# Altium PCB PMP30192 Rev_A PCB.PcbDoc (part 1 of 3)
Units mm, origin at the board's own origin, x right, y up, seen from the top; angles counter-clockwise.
Board outline 142.24 x 157.48 mm, 4 copper layers (Top Layer, Signal Layer 1, Signal Layer 2, Bottom Layer), stack 1.647 mm thick; 198 components, 99 nets, 479 pads, 192 vias.
Unrouted connection lines stored in the file: 2.
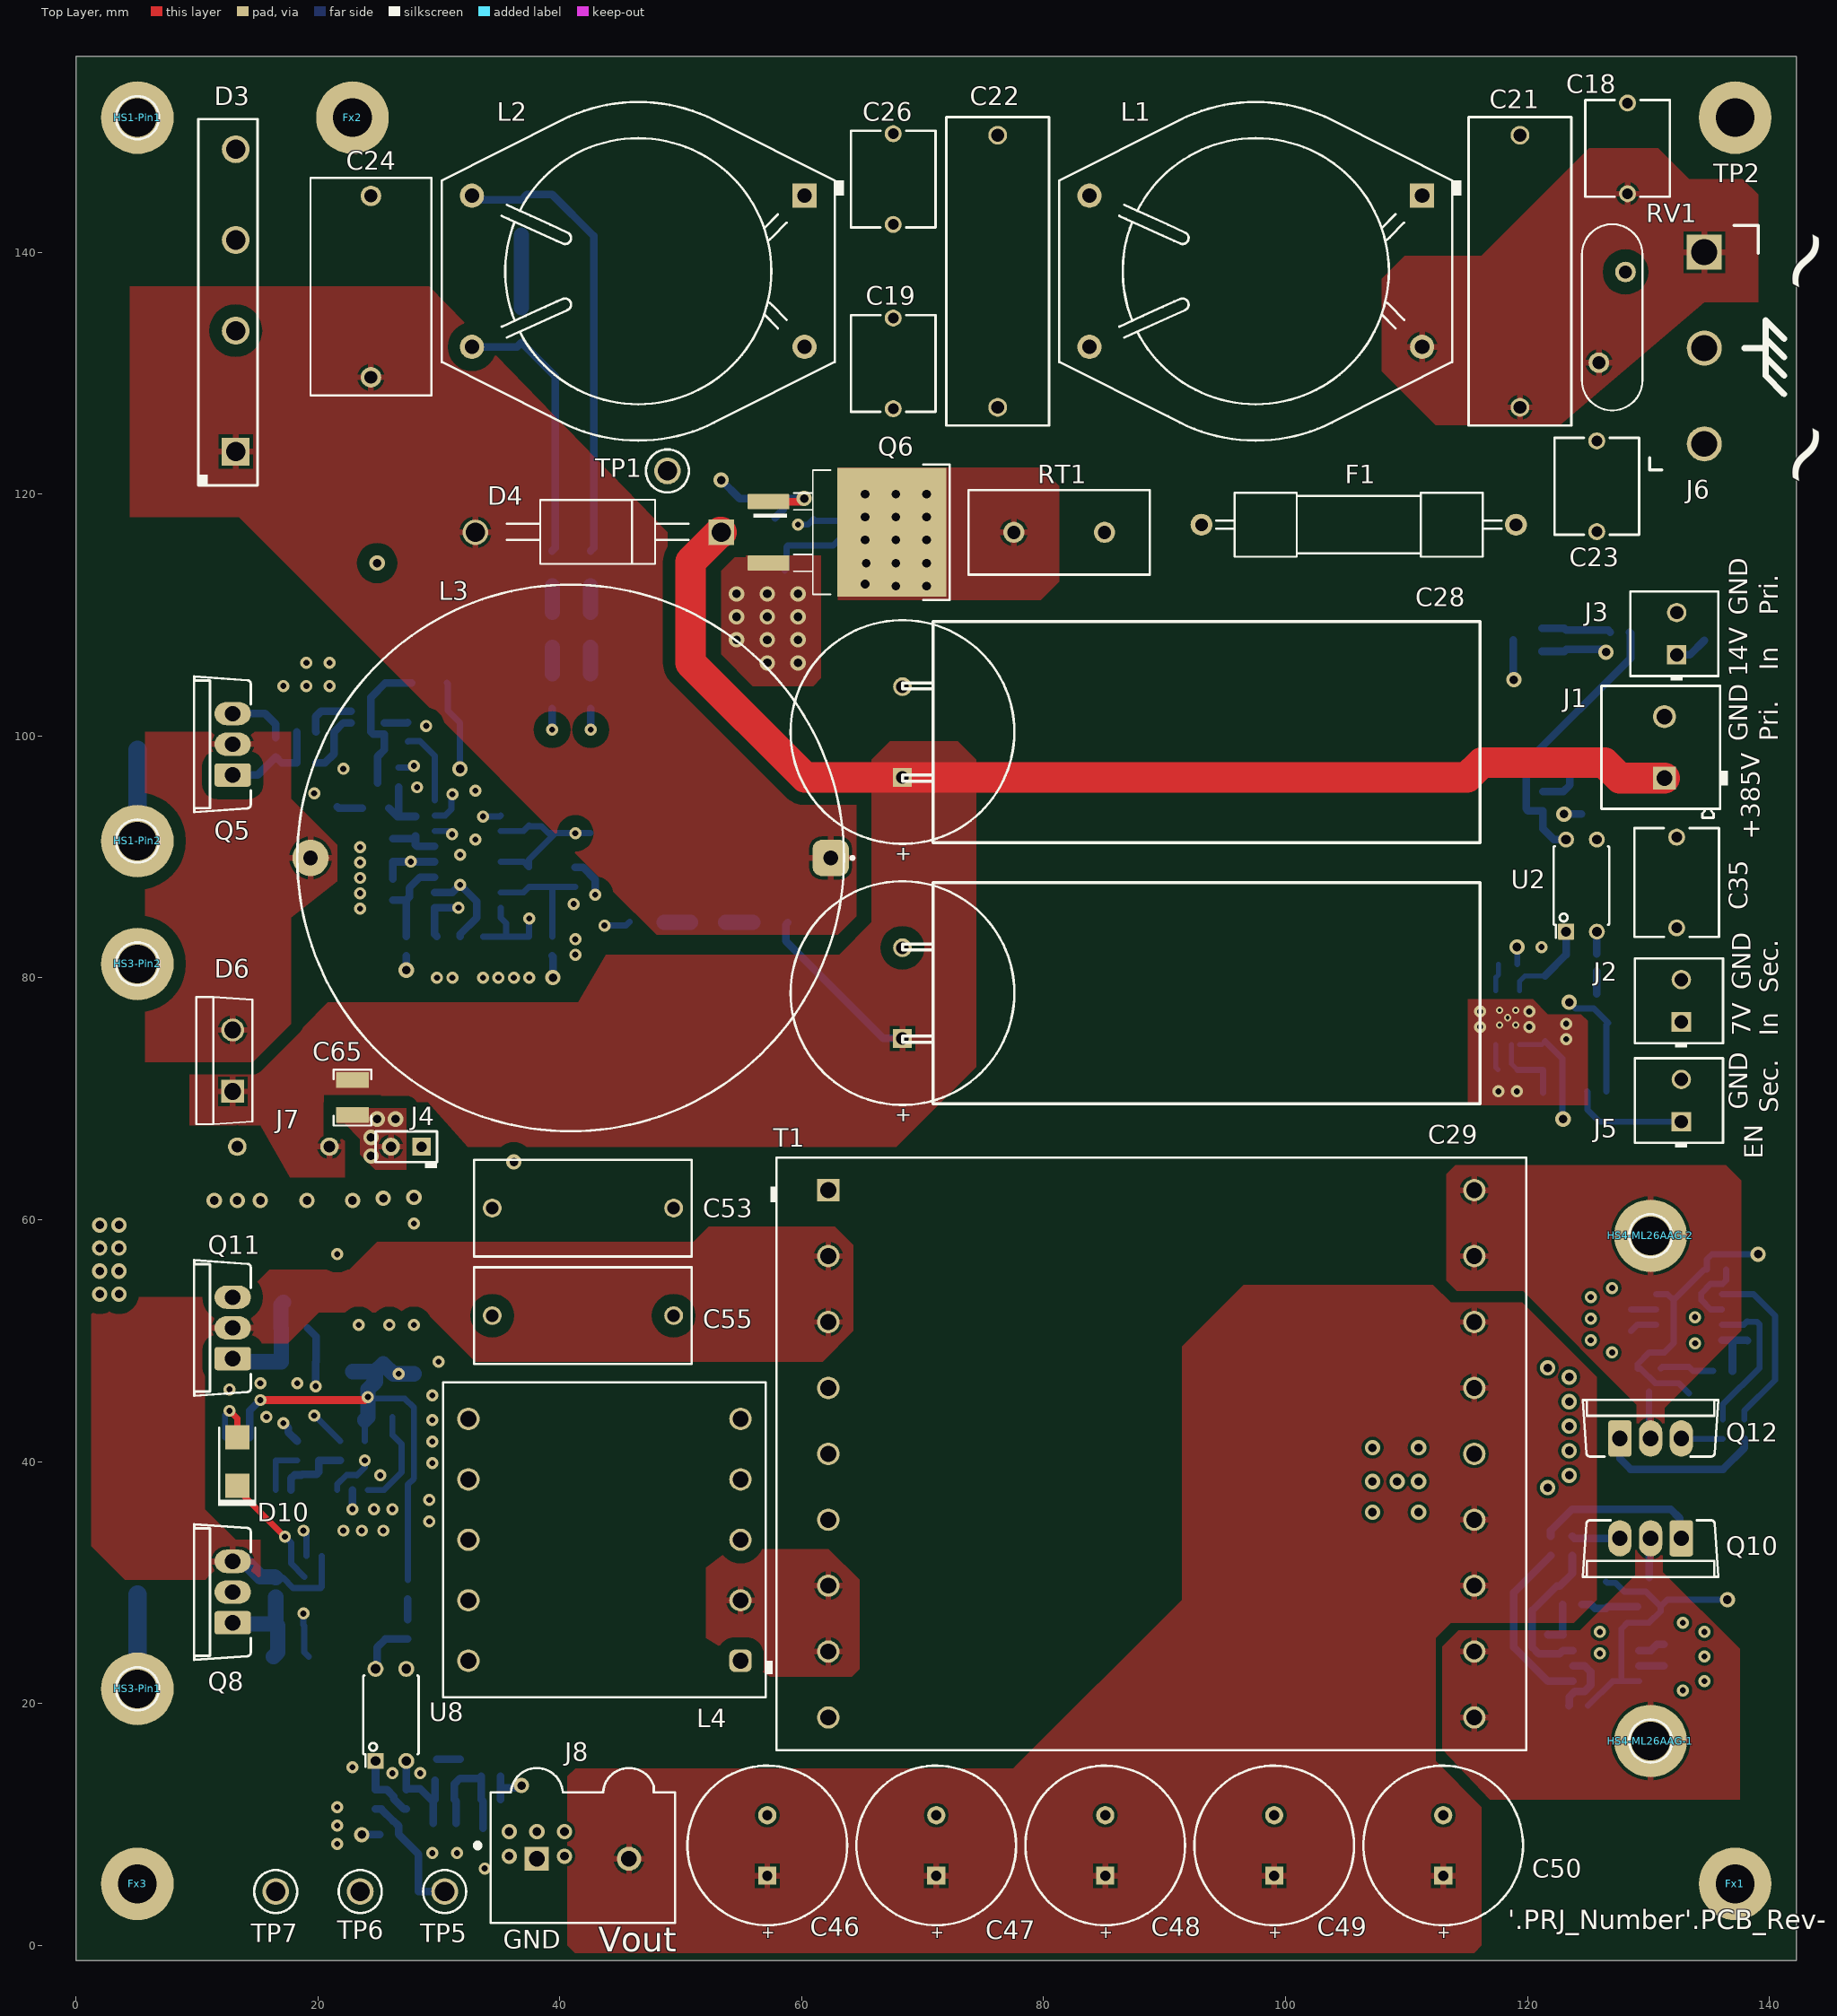
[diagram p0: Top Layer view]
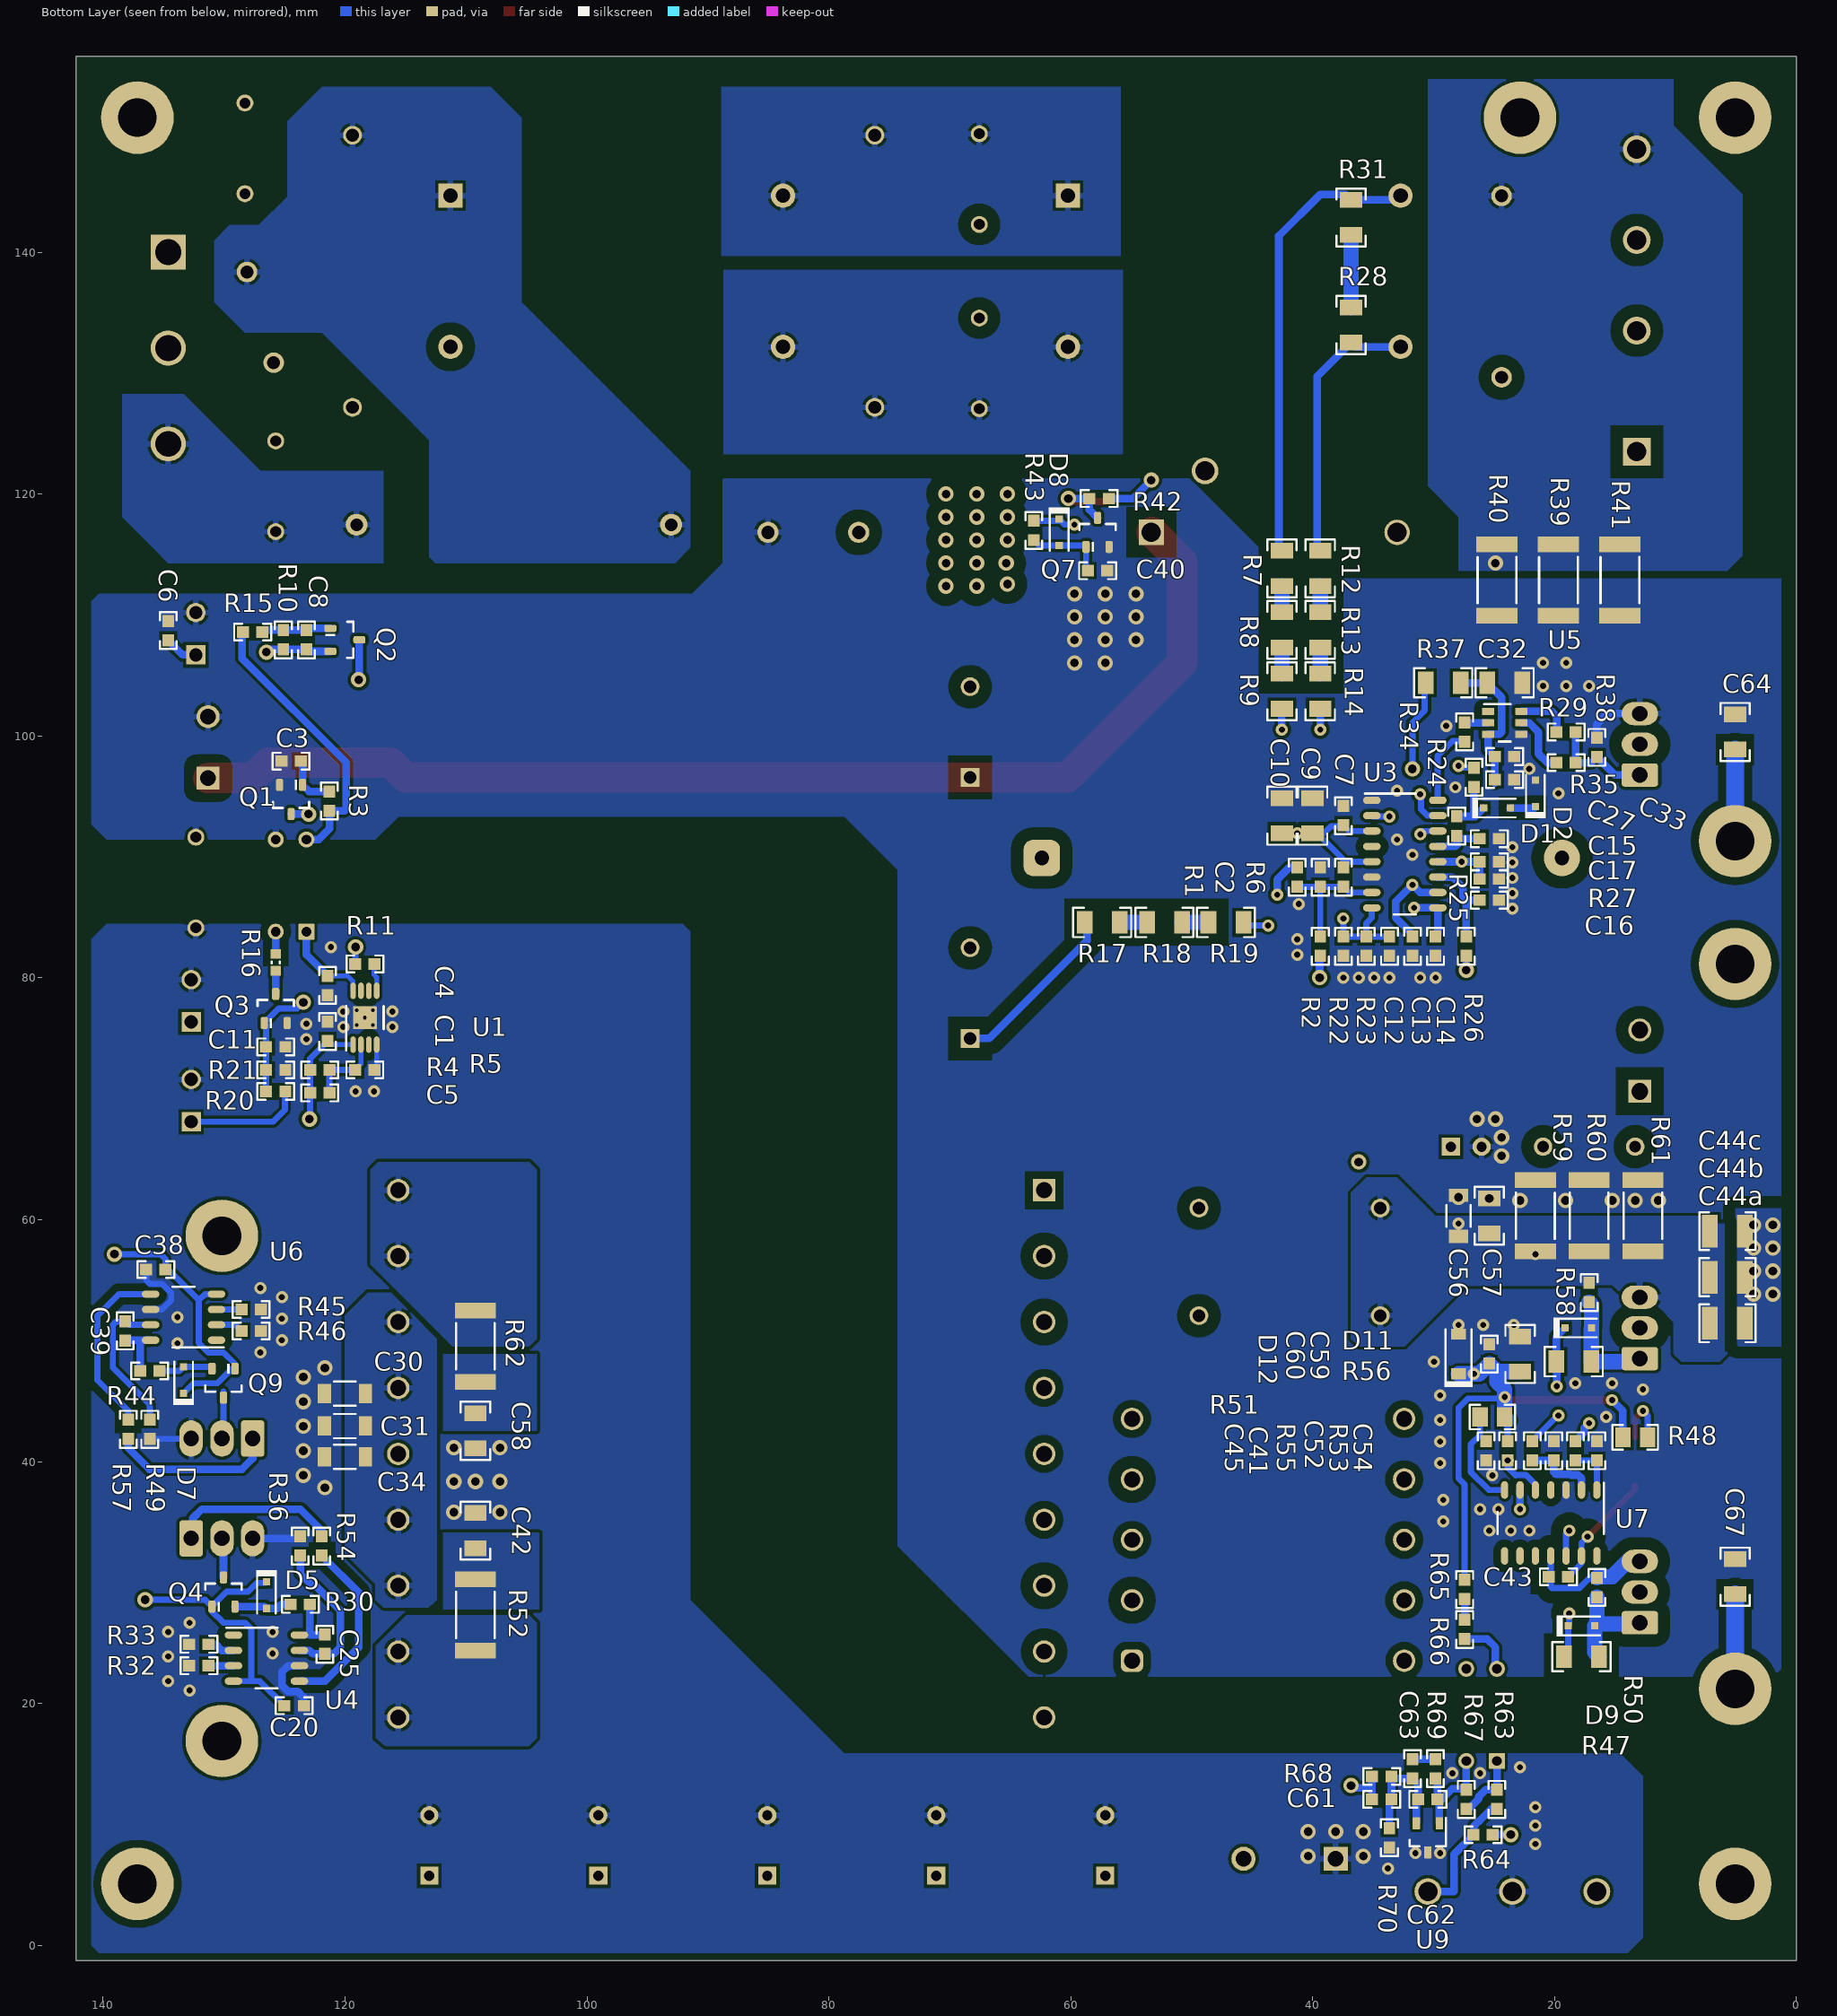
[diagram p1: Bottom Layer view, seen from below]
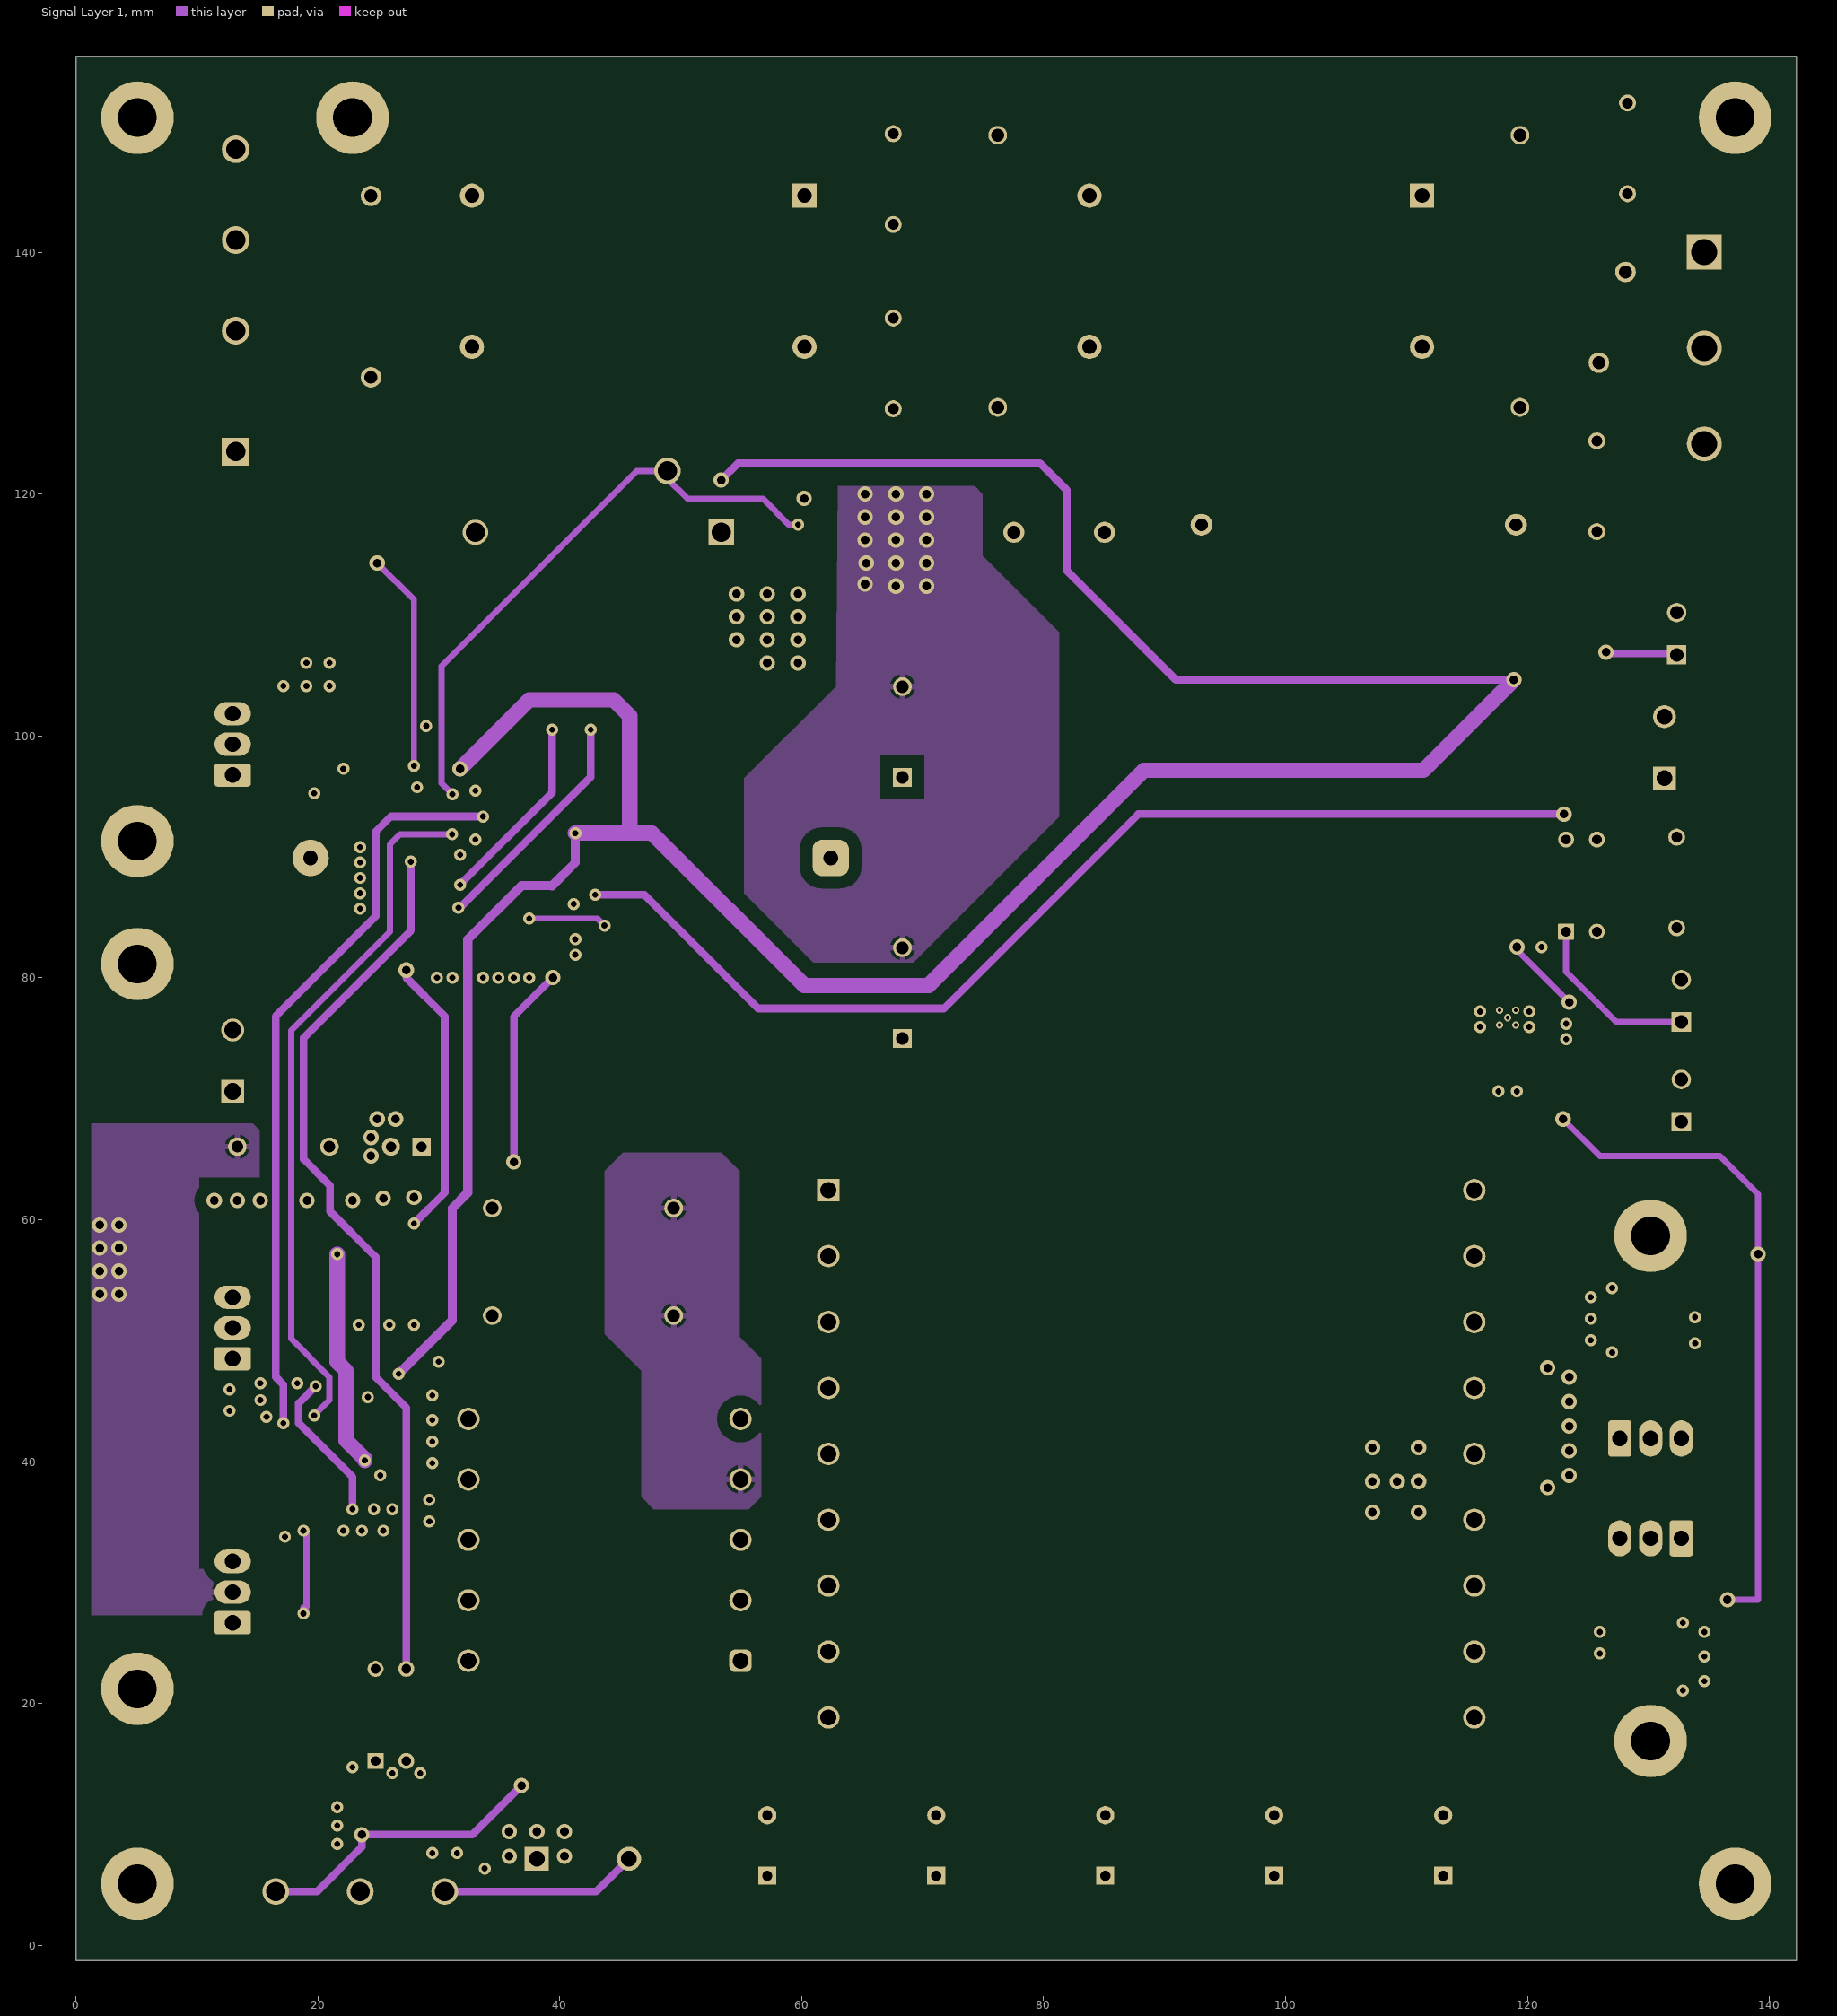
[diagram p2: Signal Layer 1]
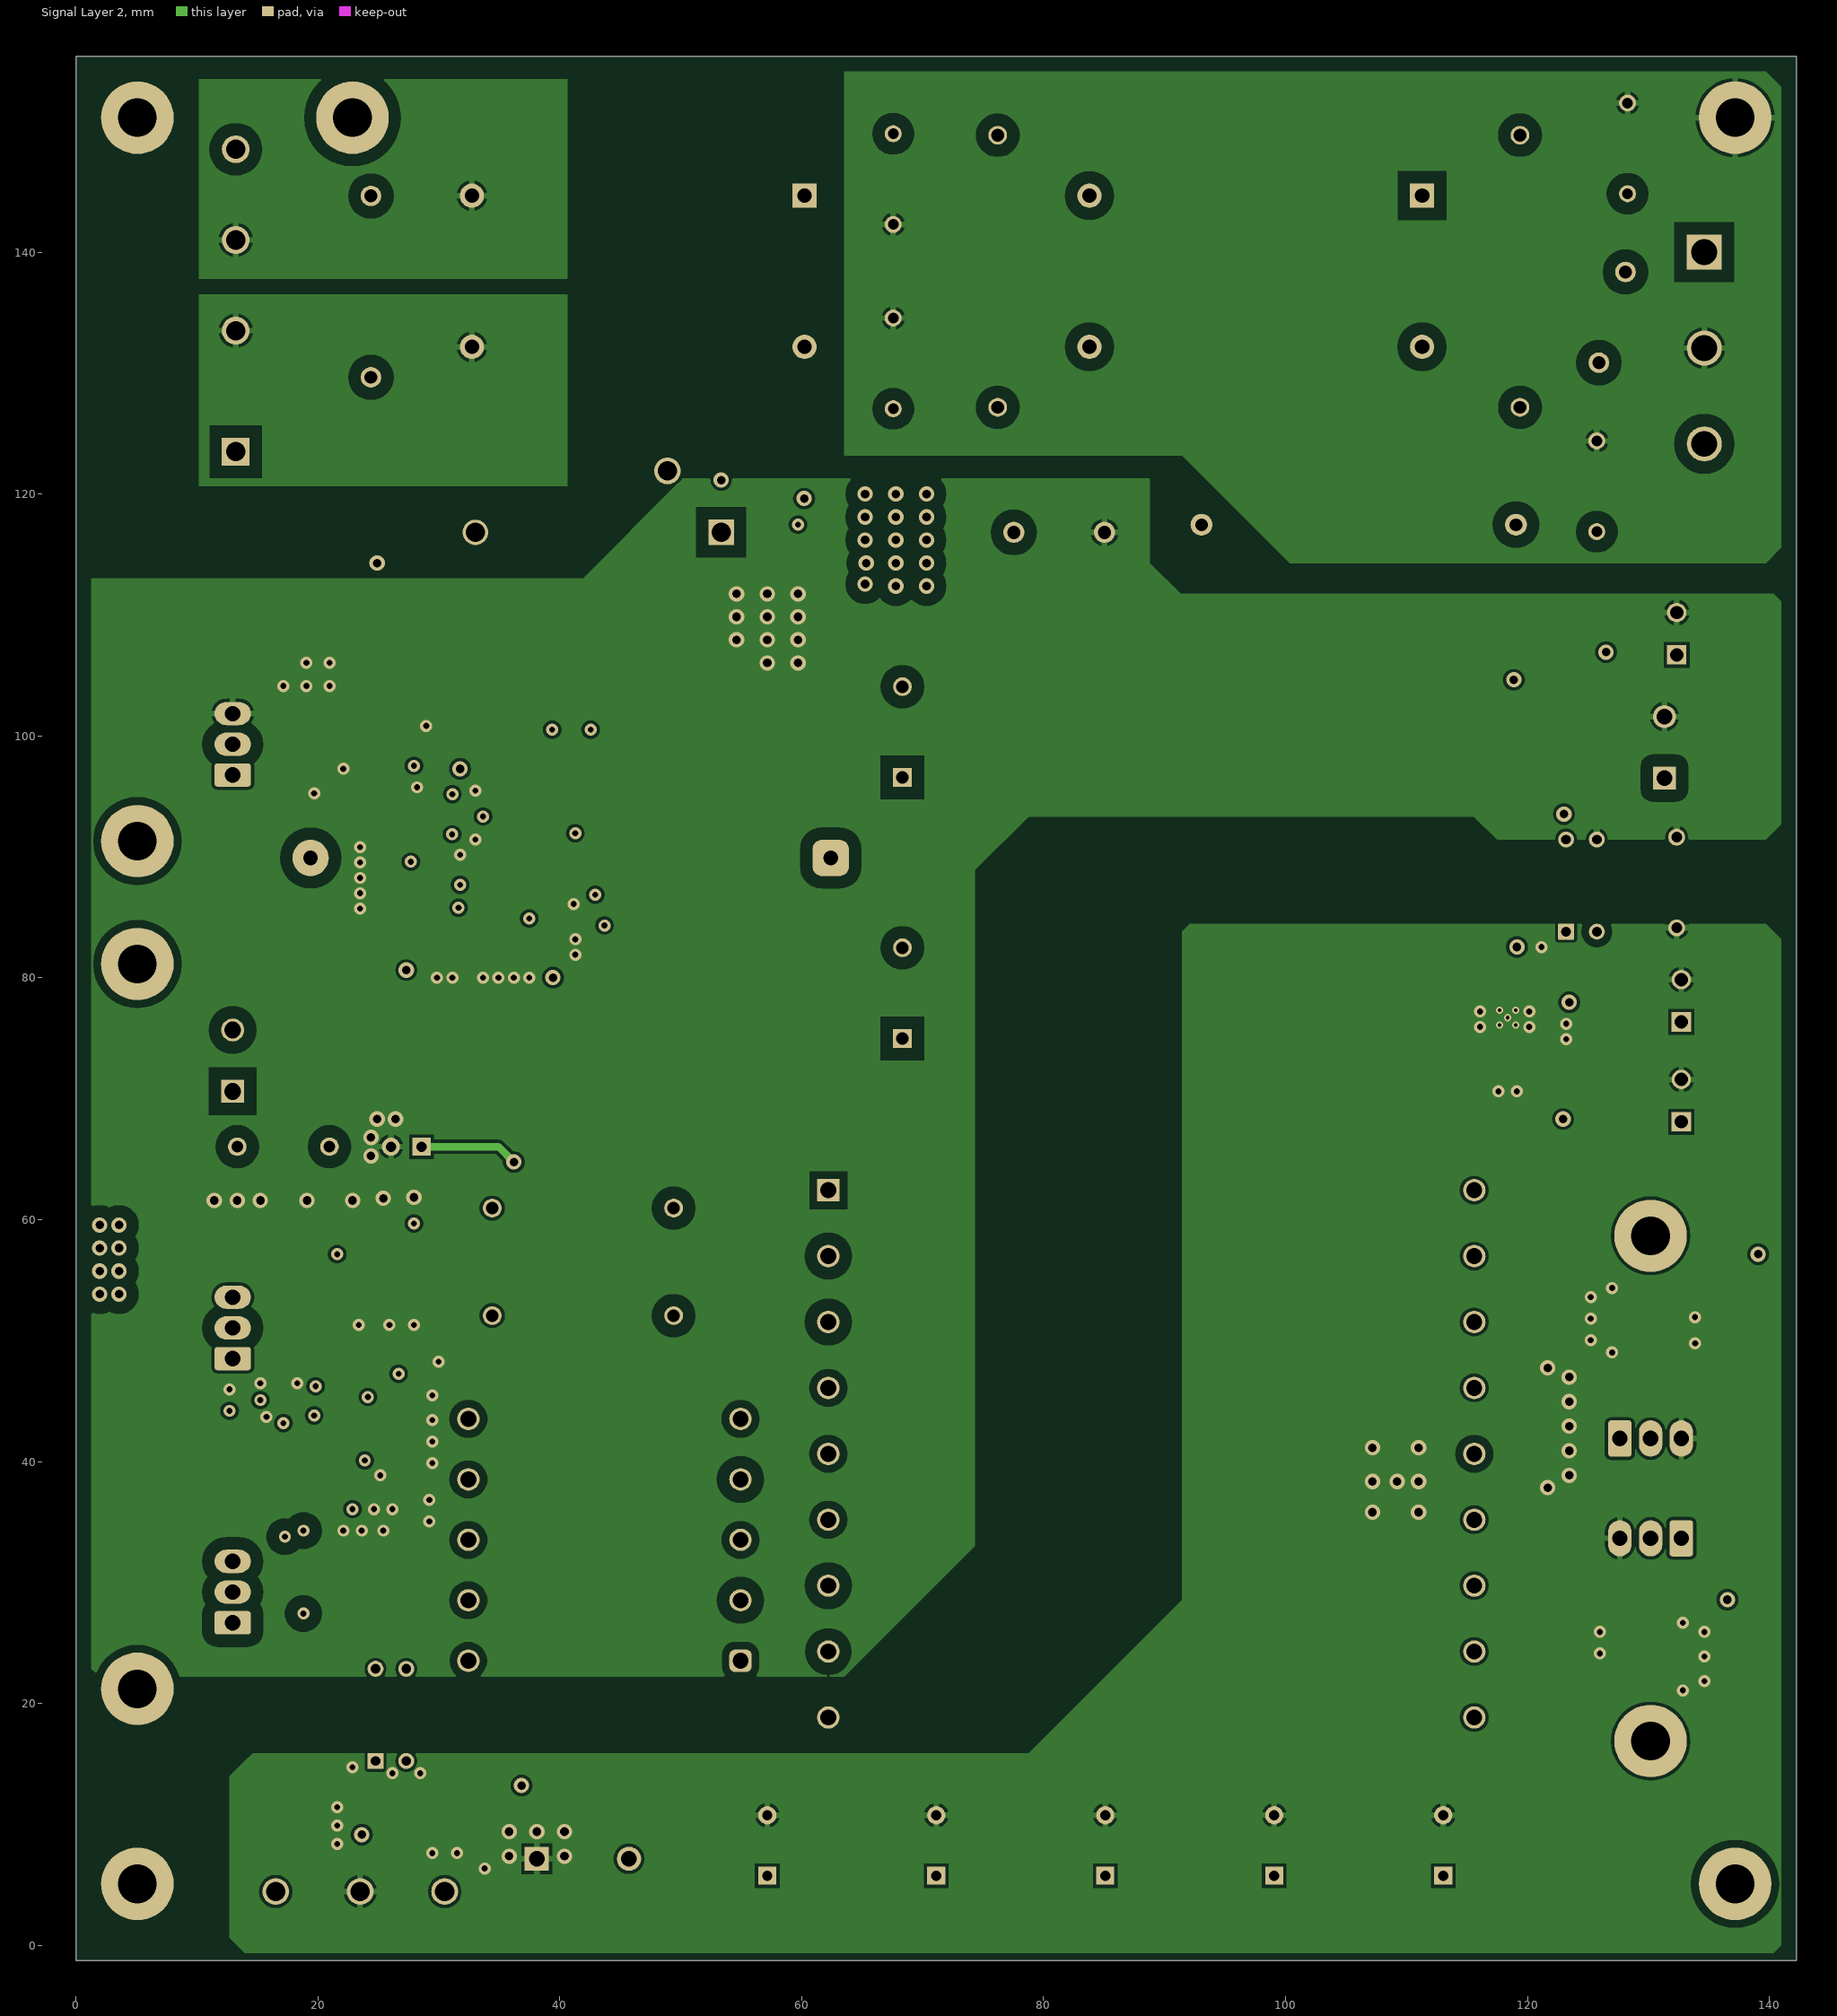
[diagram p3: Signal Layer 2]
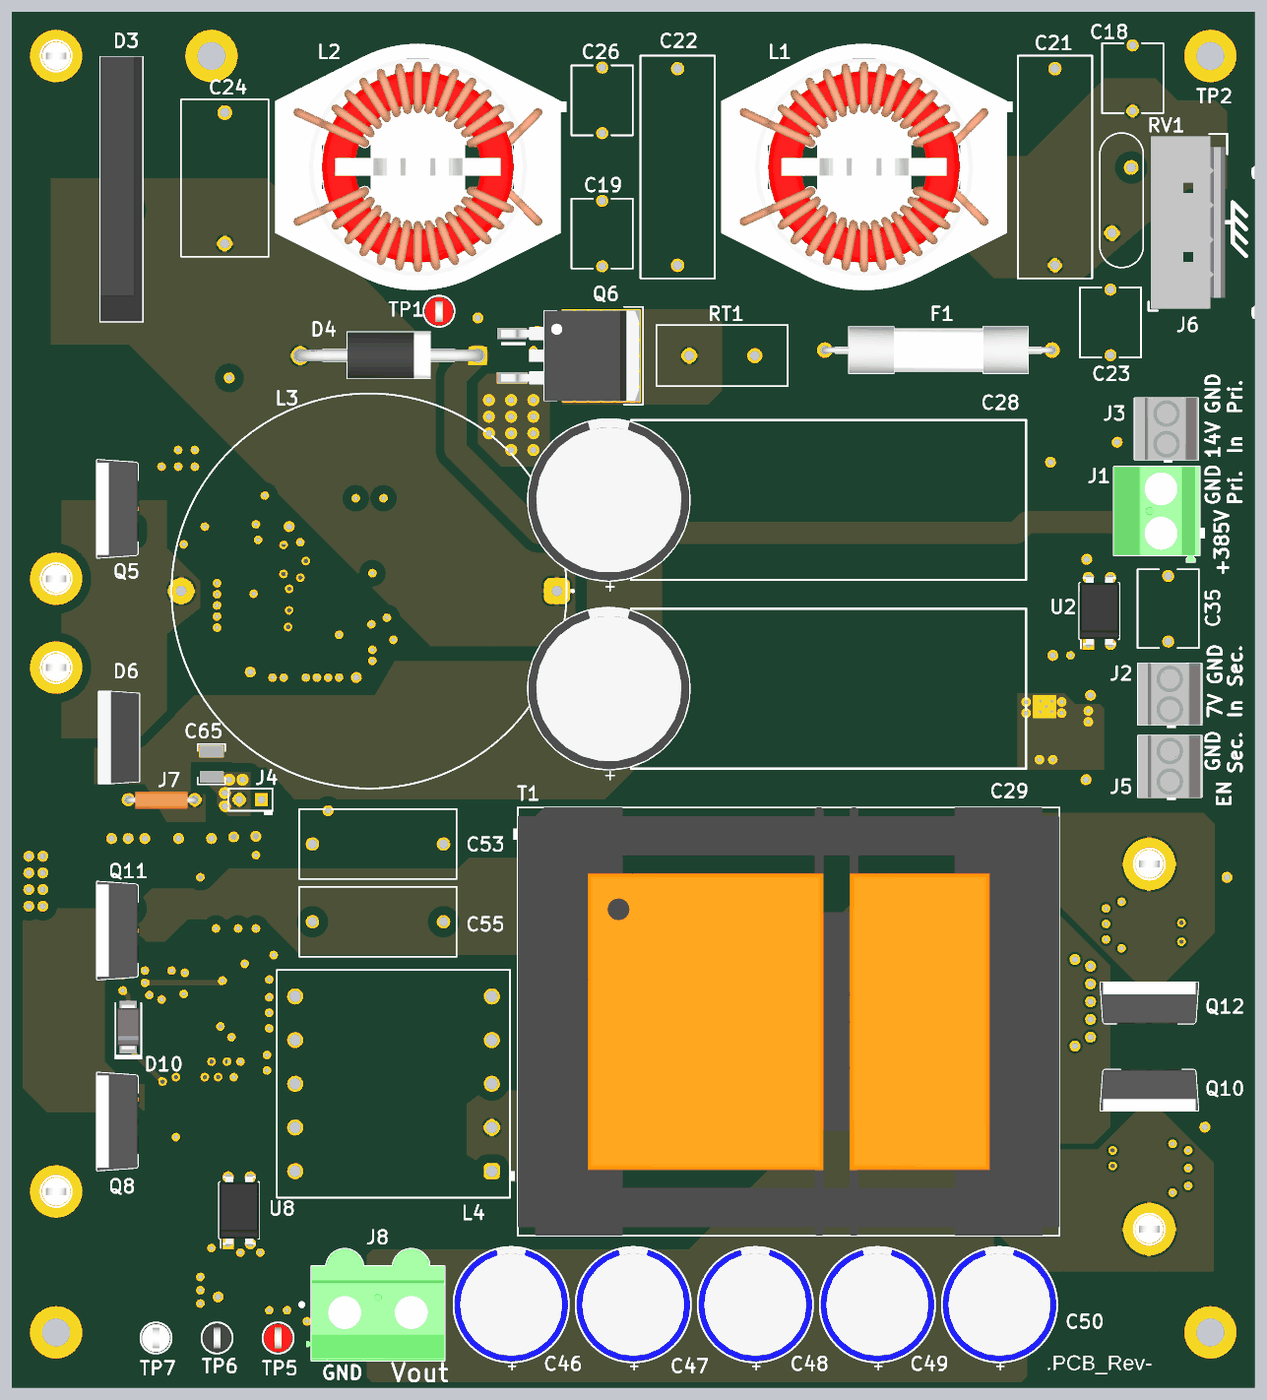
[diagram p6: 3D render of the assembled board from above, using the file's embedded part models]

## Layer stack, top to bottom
Top Solder: solder mask 0.0102, Solder Resist, Dk 3.5
Top Layer: signal copper 0.0356
Signal Layer 1: signal copper 0.036
Dielectric1: core 1.5037, FR-4, Dk 4.8
Signal Layer 2: signal copper 0.036
Bottom Layer: signal copper 0.0356
Bottom Solder: solder mask 0.0102, Solder Resist, Dk 3.5

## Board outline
0,-1.27 0,156.21 142.24,156.21 142.24,-1.27

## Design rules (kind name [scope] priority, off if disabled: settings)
AcuteAngle [All] p1: minimum=4.50000000000000E+0001 checktracksonly=FALSE
AssemblyTestPointUsage [All] p1: valid=2
BoardOutlineClearance BoardOutlineClearance_MountingHoles [OnCopper and InComponentClass('Mounting Holes')] p1: gap=1.016
BoardOutlineClearance BoardOutlineClearance_Poly [OnCopper and IsPoly] p2: gap=0.635
BoardOutlineClearance [OnCopper and Not InComponentClass('Logo') and not InComponentClass('FiducialMark') and not InRegion(1000,500,4000,800) and not InPoly] p3: gap=1.905
Clearance "Schematic Clearance Constraint_88" [InNet('NetC53_1')] p1: gap=1.016
Clearance "Schematic Clearance Constraint_84" [InNet('NetR7_1')] p2: gap=1.016
Clearance "Schematic Clearance Constraint_83" [InNet('NetR8_1')] p3: gap=1.016
Clearance "Schematic Clearance Constraint_82" [InNet('NetR12_1')] p4: gap=1.016
Clearance "Schematic Clearance Constraint_81" [InNet('NetR13_1')] p5: gap=1.016
Clearance "Schematic Clearance Constraint_80" [InNet('NetR17_2')] p6: gap=1.016
Clearance "Schematic Clearance Constraint_79" [InNet('NetR18_2')] p7: gap=1.016
Clearance "Schematic Clearance Constraint_77" [InNet('BULK')] p8: gap=1.016
Clearance "Schematic Clearance Constraint_75" [InNet('AC2')] p9: gap=1.016
Clearance "Schematic Clearance Constraint_73" [InNet('AC1')] p10: gap=1.016
Clearance "Schematic Clearance Constraint_34" [InNet('PFCGD')] p11: gap=0.254
Clearance "Schematic Clearance Constraint_33" [InNet('PFCCS')] p12: gap=0.254
Clearance "Schematic Clearance Constraint_32" [InNet('NetC3_2')] p13: gap=0.254
Clearance "Schematic Clearance Constraint_31" [InNet('NetC5_1')] p14: gap=0.254
Clearance "Schematic Clearance Constraint_30" [InNet('NetC6_1')] p15: gap=0.254
Clearance "Schematic Clearance Constraint_29" [InNet('NetC8_2')] p16: gap=0.254
Clearance "Schematic Clearance Constraint_28" [InNet('NetC11_1')] p17: gap=0.254
Clearance "Schematic Clearance Constraint_27" [InNet('NetC12_1')] p18: gap=0.254
Clearance "Schematic Clearance Constraint_26" [InNet('NetC13_1')] p19: gap=0.254
Clearance "Schematic Clearance Constraint_25" [InNet('NetC14_1')] p20: gap=0.254
Clearance "Schematic Clearance Constraint_24" [InNet('NetC15_2')] p21: gap=0.254
Clearance "Schematic Clearance Constraint_23" [InNet('NetC16_1')] p22: gap=0.254
Clearance "Schematic Clearance Constraint_22" [InNet('NetD1_1')] p23: gap=0.254
Clearance "Schematic Clearance Constraint_21" [InNet('NetJ4_1')] p24: gap=0.254
Clearance "Schematic Clearance Constraint_20" [InNet('NetQ1_3')] p25: gap=0.254
Clearance "Schematic Clearance Constraint_19" [InNet('NetQ3_3')] p26: gap=0.254
Clearance "Schematic Clearance Constraint_18" [InNet('MD_SEL')] p27: gap=0.254
Clearance "Schematic Clearance Constraint_17" [InNet('LP_ON')] p28: gap=0.254
Clearance "Schematic Clearance Constraint_15" [InNet('LLC_RCS')] p29: gap=0.254
Clearance "Schematic Clearance Constraint_14" [InNet('HIGH_POWER')] p30: gap=0.254
Clearance "Schematic Clearance Constraint_12" [InNet('GD2')] p31: gap=0.254
Clearance "Schematic Clearance Constraint_10" [InNet('GD1')] p32: gap=0.254
Clearance "Schematic Clearance Constraint_9" [InNet('FB')] p33: gap=0.254
Clearance "Schematic Clearance Constraint_8" [InNet('AC_DET')] p34: gap=0.254
Clearance "Schematic Clearance Constraint_5" [InNet('12V')] p35: gap=0.254
Clearance "Schematic Clearance Constraint_4" [InNet('7VS')] p36: gap=0.254
Clearance "Schematic Clearance Constraint_3" [InNet('5VS_ENA')] p37: gap=0.254
Clearance "Schematic Clearance Constraint_1" [InNet('5VS')] p38: gap=0.254
Clearance "Schematic Clearance Constraint_97" [InNet('NetC19_1')] p39: gap=1.016
Clearance "Schematic Clearance Constraint_96" [InNet('NetC21_2')] p40: gap=1.016
Clearance "Schematic Clearance Constraint_95" [InNet('NetC22_2')] p41: gap=1.016
Clearance "Schematic Clearance Constraint_94" [InNet('NetC23_2')] p42: gap=1.016
Clearance "Schematic Clearance Constraint_93" [InNet('NetC24_1')] p43: gap=1.016
Clearance "Schematic Clearance Constraint_92" [InNet('NetC28_2')] p44: gap=1.016
Clearance "Schematic Clearance Constraint_91" [InNet('NetC43_1')] p45: gap=1.016
Clearance "Schematic Clearance Constraint_90" [InNet('NetC43_2')] p46: gap=1.016
Clearance "Schematic Clearance Constraint_89" [InNet('NetC44a_2')] p47: gap=1.016
Clearance "Schematic Clearance Constraint_87" [InNet('NetD6_2')] p48: gap=1.016
Clearance "Schematic Clearance Constraint_86" [InNet('NetD9_1')] p49: gap=1.016
Clearance "Schematic Clearance Constraint_85" [InNet('NetD9_2')] p50: gap=1.016
Clearance "Schematic Clearance Constraint_78" [InNet('BULK')] p51: gap=1.016
Clearance "Schematic Clearance Constraint_76" [InNet('AC2')] p52: gap=1.016
Clearance "Schematic Clearance Constraint_74" [InNet('AC1')] p53: gap=1.016
Clearance "Schematic Clearance Constraint_72" [InNet('VD_SR1')] p54: gap=0.254
Clearance "Schematic Clearance Constraint_71" [InNet('NetC25_1')] p55: gap=0.254
Clearance "Schematic Clearance Constraint_70" [InNet('NetC25_2')] p56: gap=0.254
Clearance "Schematic Clearance Constraint_69" [InNet('NetC27_2')] p57: gap=0.254
Clearance "Schematic Clearance Constraint_68" [InNet('NetC39_1')] p58: gap=0.254
Clearance "Schematic Clearance Constraint_67" [InNet('NetR35_1')] p59: gap=0.254
Clearance "Schematic Clearance Constraint_66" [InNet('NetC39_2')] p60: gap=0.254
Clearance "Schematic Clearance Constraint_65" [InNet('NetC40_2')] p61: gap=0.254
Clearance "Schematic Clearance Constraint_64" [InNet('NetC42_2')] p62: gap=0.254
Clearance "Schematic Clearance Constraint_63" [InNet('NetC45_2')] p63: gap=0.254
Clearance "Schematic Clearance Constraint_62" [InNet('NetC52_1')] p64: gap=0.254
Clearance "Schematic Clearance Constraint_61" [InNet('NetC54_2')] p65: gap=0.254
Clearance "Schematic Clearance Constraint_60" [InNet('NetC58_2')] p66: gap=0.254
Clearance "Schematic Clearance Constraint_59" [InNet('NetC61_1')] p67: gap=0.254
Clearance "Schematic Clearance Constraint_58" [InNet('NetC61_2')] p68: gap=0.254
Clearance "Schematic Clearance Constraint_57" [InNet('NetC62_1')] p69: gap=0.254
Clearance "Schematic Clearance Constraint_56" [InNet('NetC63_1')] p70: gap=0.254
Clearance "Schematic Clearance Constraint_55" [InNet('NetD5_2')] p71: gap=0.254
Clearance "Schematic Clearance Constraint_54" [InNet('NetD7_2')] p72: gap=0.254
Clearance "Schematic Clearance Constraint_53" [InNet('NetD10_2')] p73: gap=0.254
Clearance "Schematic Clearance Constraint_52" [InNet('NetD11_1')] p74: gap=0.254
Clearance "Schematic Clearance Constraint_51" [InNet('NetD11_2')] p75: gap=0.254
Clearance "Schematic Clearance Constraint_50" [InNet('NetQ5_1')] p76: gap=0.254
Clearance "Schematic Clearance Constraint_49" [InNet('NetQ6_1')] p77: gap=0.254
Clearance "Schematic Clearance Constraint_48" [InNet('NetQ10_1')] p78: gap=0.254
Clearance "Schematic Clearance Constraint_46" [InNet('NetQ12_1')] p79: gap=0.254
Clearance "Schematic Clearance Constraint_45" [InNet('NetR29_1')] p80: gap=0.254
Clearance "Schematic Clearance Constraint_44" [InNet('NetR32_2')] p81: gap=0.254
Clearance "Schematic Clearance Constraint_42" [InNet('NetR33_2')] p82: gap=0.254
Clearance "Schematic Clearance Constraint_41" [InNet('NetR34_1')] p83: gap=0.254
Clearance "Schematic Clearance Constraint_40" [InNet('NetR45_2')] p84: gap=0.254
Clearance "Schematic Clearance Constraint_39" [InNet('NetR46_2')] p85: gap=0.254
Clearance "Schematic Clearance Constraint_38" [InNet('NetR63_1')] p86: gap=0.254
Clearance "Schematic Clearance Constraint_37" [InNet('NetR65_2')] p87: gap=0.254
Clearance "Schematic Clearance Constraint_36" [InNet('NetR66_2')] p88: gap=0.254
Clearance "Schematic Clearance Constraint_35" [InNet('29V')] p89: gap=0.254
Clearance "Schematic Clearance Constraint_16" [InNet('LLC_RCS')] p90: gap=0.254
Clearance "Schematic Clearance Constraint_13" [InNet('GD2')] p91: gap=0.254
Clearance "Schematic Clearance Constraint_11" [InNet('GD1')] p92: gap=0.254
Clearance "Schematic Clearance Constraint_7" [InNet('12V')] p93: gap=0.254
Clearance "Schematic Clearance Constraint_2" [InNet('5VS')] p94: gap=0.254
Clearance "Schematic Clearance Constraint_47" [InNet('NetL4_2')] p95: gap=1.016
Clearance "Schematic Clearance Constraint_43" [InNet('VD_SR2')] p96: gap=0.254
Clearance "Schematic Clearance Constraint_6" [InNet('PFCCS')] p97: gap=0.254
Clearance "Schematic Clearance Constraint" [InNet('NetC18_1')] p98: gap=1.016
Clearance Clearance_Keepouts [((IsTrack Or IsArc) And Not InPoly) And IsFree and IsKeepOut vs ((IsTrack Or IsArc) And Not InPoly) And IsFree and IsKeepOut] p99: gap=0
Clearance Clearance_Poly [InPolygon] p100: gap=0.635
Clearance [All] p101: gap=0.2
ComponentClearance ComponentClearance_MountingHoles_FiducialMarks [InComponentClass('Mounting Holes') vs InComponentClass('FiducialMark')] p1: gap=1.27 collisioncheckmode=3 verticalgap=0.254 showdistances=FALSE
ComponentClearance ComponentClearance_Shunt [InComponentClass('Header') vs InComponentClass('Shunt')] p2: gap=0 collisioncheckmode=3 verticalgap=0 showdistances=FALSE
ComponentClearance ComponentClearance_Logo [InComponentClass('Logo')] p3: gap=1.27 collisioncheckmode=3 verticalgap=0.254 showdistances=FALSE
ComponentClearance ComponentClearance_ScrewToNut [(HasFootprint('NY PMS 440 0025 PH')) vs (HasFootprint('Keystone_1902C'))] p4: gap=0.127 collisioncheckmode=3 verticalgap=0.254 showdistances=FALSE
ComponentClearance ComponentClearance_MountingHoles [InComponentClass('Mounting Holes')] p5: gap=6.35 collisioncheckmode=3 verticalgap=2540 showdistances=FALSE
ComponentClearance ComponentClearance_SmallPassives [HasFootprint('0201*') or HasFootprint('0402*') or HasFootprint('0508') or HasFootprint('0603*') or HasFootprint('0612') or HasFootprint('0805*') or HasFootprint('0815*') or HasFootprint('0830*') or HasFootprint('1206*') or HasFootprint('1210*') or HasFootprint('1808*') or HasFootprint('1812*') or HasFootprint('1825*') or HasFootprint('2010*') or HasFootprint('2220*') or HasFootprint('2225*') or HasFootprint('2512*') or HasFootprint('2728*') or HasFootprint('3518*') vs HasFootprint('0201*') or HasFootprint('0402*') or HasFootprint('0508') or HasFootprint('0603*') or HasFootprint('0612') or HasFootprint('0805*') or HasFootprint('0815*') or HasFootprint('0830*') or HasFootprint('1206*') or HasFootprint('1210*') or HasFootprint('1808*') or HasFootprint('1812*') or HasFootprint('1825*') or HasFootprint('2010*') or HasFootprint('2220*') or HasFootprint('2225*') or HasFootprint('2512*') or HasFootprint('2728*') or HasFootprint('3518*')] p6: gap=0.38 collisioncheckmode=3 verticalgap=0.254 showdistances=FALSE
ComponentClearance ComponentClearance_THtoSMT [IsThruComponent vs IsSMTComponent] p7: gap=1.016 collisioncheckmode=3 verticalgap=0.762 showdistances=FALSE
ComponentClearance ComponentClearance_THtoTH [IsThruComponent vs IsThruComponent] p8: gap=0.762 collisioncheckmode=3 verticalgap=0.762 showdistances=FALSE
ComponentClearance [All] p9: gap=0.762 collisioncheckmode=3 verticalgap=0.254 showdistances=FALSE
DiffPairsRouting [All] p1: maxlimit=2.54 minlimit=0.254 mostfreqgap=0.254 toplayer_minwidth=0.381 toplayer_maxwidth=0.381 toplayer_prefwidth=0.381 midlayer1_minwidth=0.381 midlayer1_maxwidth=0.381 midlayer1_prefwidth=0.381 midlayer2_minwidth=0.381 midlayer2_maxwidth=0.381 midlayer2_prefwidth=0.381 bottomlayer_minwidth=0.381 bottomlayer_maxwidth=0.381 bottomlayer_prefwidth=0.381 maxuncoupledlength=25.4
FabricationTestPointUsage TestPointUsage [All] p1: valid=2 allowmultiple=FALSE
FabricationTestpoint Testpoint [All] p1: side=3 testpointundercomponent=TRUE minsize=1.016 maxsize=2.54 preferedsize=1.524 minholesize=0 maxholesize=1.016 preferedholesize=0.813 testpointgrid=0.025 allowsidetop=TRUE allowsidebottom=TRUE usegrid=TRUE gridtolerance=0
FanoutControl Fanout_LCC [IsLCC] p1: bgadir=Out bgaviamode=Centered fanoutstyle=Auto fanoutdirection=Alternating viagrid=0.025 // Fanout_LCC (Default Rule)
FanoutControl Fanout_BGA [IsBGA] p2: bgadir=Out bgaviamode=Centered fanoutstyle=Auto fanoutdirection=Alternating viagrid=0.025 // Fanout_BGA (Default Rule)
FanoutControl Fanout_Default [All] p4: bgadir=Out bgaviamode=Centered fanoutstyle=Auto fanoutdirection=Alternating viagrid=0.025 // Fanout_Default (Default Rule)
FanoutControl Fanout_Small [(CompPinCount < 5)] p5: bgadir=Out bgaviamode=Centered fanoutstyle=Auto fanoutdirection=OutThenIn viagrid=0.025 // Fanout_Small (Default Rule)
HoleSize [All] p1: absolutevalues=TRUE maxlimit=6.375 minlimit=0.3 maxpercent=80.000 minpercent=20.000
MinimumAnnularRing MinimumAnnularRing_ThermalPadVias [IsVia and InAnyComponent] p1: minimumring=0.15
MinimumAnnularRing [All] p2: minimumring=0.203
MinimumSolderMaskSliver MinimumSolderMaskSliver_Logo [InComponentClass('Logo') vs InComponentClass('Logo')] p1: minsoldermaskwidth=0.018
MinimumSolderMaskSliver [All] p2: minsoldermaskwidth=0.1
PlaneConnect [All] p1: planeconnectstyle=Relief reliefexpansion=0.254 reliefentries=4 reliefconductorwidth=0.254 reliefairgap=0.254
PolygonConnect PolygonConnect_Via [IsVia] p1: connectstyle=Direct reliefconductorwidth=0.254 reliefentries=4 polygonreliefangle="90 Angle" airgapwidth=0.254
PolygonConnect PolygonConnect_SMT_pin [IsSMTPin] p2: connectstyle=Direct reliefconductorwidth=0.254 reliefentries=4 polygonreliefangle="90 Angle" airgapwidth=0.254
PolygonConnect PolygonConnect_General [All] p3: connectstyle=Relief reliefconductorwidth=0.508 reliefentries=4 polygonreliefangle="90 Angle" airgapwidth=0.254
RoutingVias ThermalPadVias [IsVia and InAnyComponent] p1: holewidth=0.2 width=0.5 viastyle="Through Hole" minholewidth=0.2 minwidth=0.5 maxholewidth=0.33 maxwidth=0.6
RoutingVias [All] p2: holewidth=0.406 width=0.864 viastyle="Through Hole" minholewidth=0.2 minwidth=0.66 maxholewidth=1.016 maxwidth=1.651
SilkToBoardRegionClearance [Not ((IsComment or IsDesignator) And (Hide <> 'False')) and not InRegion(1000,500,4000,800)] p1:
SilkToSilkClearance SilkToSilkClearance_Pb-FreeLogo [(HasFootprint('Pb-Free_Overlay_Medium') OR HasFootprint('Pb-Free_Overlay_Small')) vs (HasFootprint('Pb-Free_Overlay_Medium') OR HasFootprint('Pb-Free_Overlay_Small'))] p1: silktosilkclearance=0
SilkToSilkClearance [All] p2: silktosilkclearance=0.102
SilkToSolderMaskClearance SilkToComponentPadClearance [(IsPad or IsFill or IsRegion) and InAnycomponent] p1: minsilkscreentomaskgap=0.127 clearancetoexposedcopper=TRUE
SilkToSolderMaskClearance "Silk to Solder Mask Opening" [All] p2: minsilkscreentomaskgap=0.102 clearancetoexposedcopper=FALSE
SolderMaskExpansion [All] p1: expansion=0.05
Width [All] p1: maxlimit=2.54 minlimit=0.152 preferedwidth=0.254 checkconnectedcopper=TRUE
15 further rules are at their usual default settings.

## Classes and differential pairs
component class Header: J4
component class "PMP30192 Rev_A Modulator Schematic": C1 C2 C3 C4 C5 C6 C7 C8 C9 C10 C11 C12 C13 C14 C15 C16 C17 D1 D2 J2 J3 J4 J5 Q1 Q2 Q3 R1 R2 R3 R4 R5 R6 R7 R8 R9 R10 R11 R12 R13 R14 R15 R16 R17 R18 R19 R20 R21 R22 R23 R24 R25 R26 R27 TP1 U1 U2 U3
component class "PMP30192 Rev_A PFC plus LLC Stage Schematic": C18 C19 C20 C21 C22 C23 C24 C25 C26 C27 C28 C29 C30 C31 C32 C33 C34 C35 C38 C39 C40 C41 C42 C43 C44a C44b C44c C45 C46 C47 C48 C49 C50 C52 C53 C54 C55 C56 C57 C58 C59 C60 C61 C62 C63 C64 C65 C67 D3 D4 D5 D6 D7 D8 D9 D10 D11 D12 F1 Fx1 Fx2 Fx3 HS1-Pin1 HS1-Pin2 HS3-Pin1 HS3-Pin2 HS4-ML26AAG-1 HS4-ML26AAG-2 J1 J6 J7 J8 L1 L2 L3 L4 Q4 Q5 Q6 Q7 Q8 Q9 Q10 Q11 Q12 R28 R29 R30 R31 R32 R33 R34 R35 R36 R37 R38 R39 R40 R41 R42 R43 R44 R45 R46 R47 R48 R49 R50 R51 R52 R53 R54 R55 R56 R57 R58 R59 R60 R61 R62 R63 R64 R65 R66 R67 R68 R69 R70 RT1 RV1 T1 TP2 TP5 TP6 TP7 U4 U5 U6 U7 U8 U9

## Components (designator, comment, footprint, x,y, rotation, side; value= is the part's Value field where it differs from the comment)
C1 "GRM188R61A475ME15" 0603 121.45,75.565 r90 bottom
C2 "UMK107AB7105KA-T" 0603 39.37,88.332 r270 bottom
C3 "06031C103JAT2A" 0603 124.46,97.925 r180 bottom
C4 "06035C104KAT2A" 0603 121.45,79.375 r270 bottom
C5 "06031C103JAT2A" 0603 122.085,70.485 r0 bottom
C6 "06035C104KAT2A" 0603 134.62,108.712 r90 bottom
C7 "06035C104KAT2A" 0603 37.465,93.412 r90 bottom
C8 "06031C103JAT2A" 0603 123.19,107.95 r90 bottom
C9 "GMK316AB7106KL" 1206 40.005,93.412 r270 bottom
C10 "GMK316AB7106KL" 1206 42.545,93.412 r270 bottom
C11 "06033C101KAT2A" 0603 125.73,74.295 r180 bottom
C12 "C0603C471K5RACTU" 0603 33.655,82.617 r270 bottom
C13 "C0603C471K5RACTU" 0603 31.75,82.617 r270 bottom
C14 "C0603C471K5RACTU" 0603 29.845,82.617 r270 bottom
C15 "C0603C102K5RACTU" 0603 25.4,91.507 r0 bottom
C16 "06035C104KAT2A" 0603 25.4,86.427 r180 bottom
C17 "C0603C222K5RACTU" 0603 25.4,89.602 r180 bottom
C18 "DE6B3KJ101KN3A" B_800x700x800 128.27,148.59 r90 top
C19 "DE6B3KJ221KN3A" B_800x700x800 67.564,130.81 r90 top
C20 "C0603C105K8PACTU" 0603 124.206,19.812 r180 bottom
C21 "ECQ-U2A474ML" CAPRR2250W80L2550T850H1750 119.38,138.43 r90 top
C22 "ECQ-U2A474ML" CAPRR2250W80L2550T850H1750 76.2,138.43 r90 top
C23 "DE6B3KJ101KN3A" B_800x700x800 125.73,120.65 r270 top
C24 "ECQ-U2A334ML" CAPRR1500W80L1750T950H1750 24.384,137.16 r90 top
C25 "C0603C470J5GACTU" 0603 121.666,24.892 r90 bottom
C26 "DE6B3KJ221KN3A" B_800x700x800 67.564,146.05 r90 top
C27 "UMK107AB7105KA-T" 0603 24.138,96.393 r0 bottom
C28 "450TXW150MEFC18X45" KXW_1800x4500 68.326,100.33 r90 top
C29 "450TXW150MEFC18X45" KXW_1800x4500 68.326,78.74 r90 top
C30 "C3216X5R1H106K160AB" 1206_180 120.015,45.619 r0 bottom
C31 "C3216X5R1H106K160AB" 1206_180 120.015,42.939 r0 bottom
C32 "GMK316AB7106KL" 1206 24.13,104.394 r0 bottom
C33 "06035C104KAT2A" 0603 24.138,98.298 r180 bottom
C34 "C3216X5R1H106K160AB" 1206_180 120.015,40.399 r0 bottom
C35 "DE6E3KJ222MN3A" E_900x700x900 132.334,87.884 r90 top
C38 "C0603C105K8PACTU" 0603 135.636,55.88 r0 bottom
C39 "C0603C470J5GACTU" 0603 138.176,50.8 r270 bottom
C40 "UMK107AB7105KA-T" 0603 57.785,113.665 r0 bottom
C41 "UMK107AB7105KA-T" 0603 23.876,40.894 r90 bottom
C42 "Used in BOM report" 1206 109.22,34.29 r270 bottom
C43 "06035C104KAT2A" 0603 19.685,30.48 r0 bottom
C44a "GRM32DR72J473KW01L" 1210_220 5.715,51.435 r180 bottom
C44b "GRM32DR72J473KW01L" 1210_220 5.715,55.245 r180 bottom
C44c "GRM32DR72J473KW01L" 1210_220 5.715,59.055 r180 bottom
C45 "UMK107AB7105KA-T" 0603 25.654,40.894 r90 bottom
C46 "50ZLH470M12.5X20" ZLH_1250x2500 57.15,8.255 r90 top
C47 "50ZLH470M12.5X20" ZLH_1250x2500 71.12,8.255 r90 top
C48 "50ZLH470M12.5X20" ZLH_1250x2500 85.09,8.255 r90 top
C49 "50ZLH470M12.5X20" ZLH_1250x2500 99.06,8.255 r90 top
C50 "50ZLH470M12.5X20" ZLH_1250x2500 113.03,8.255 r90 top
C52 "06035A101FAT2A" 0603 20.066,40.894 r90 bottom
C53 "121MPE183J" CAPRR1500W80L1800T800H1550 41.91,60.96 r180 top
C54 "06035A101FAT2A" 0603 16.51,40.894 r270 bottom
C55 "121MPE153J" CAPRR1500W80L1800T800H1550 41.91,52.07 r180 top
C56 "C3216X6S1A226M160AB" 1206_180 27.94,60.325 r90 bottom
C57 "C3216X5R1C476M160AB" 1206 25.4,60.325 r90 bottom
C58 "Used in BOM report" 1206 109.22,42.545 r90 bottom
C59 "GMK316AB7106KL" 1206 22.86,48.895 r270 bottom
C60 "06035C104KAT2A" 0603 25.4,48.895 r90 bottom
C61 "GRM1885C1H221JA01D" 0603 34.29,12.065 r180 bottom
C62 "06033C101KAT2A" 0603 30.48,12.065 r0 bottom
C63 "C0603C222K5RACTU" 0603 31.75,14.605 r270 bottom
C64 "GRM31BR72J102KW01L" 1206 5.08,100.33 r90 bottom
C65 "GRM32DR72J473KW01L" 1210_220 22.86,70.104 r90 top
C67 "GRM31BR72J102KW01L" 1206 5.08,30.48 r90 bottom
D1 "BAS316,115" sod-323 24.765,94.047 r180 bottom
D2 "BAS316,115" sod-323 21.59,95.25 r90 bottom
D3 "GBJL2006-BP" GBJ 13.208,136.017 r90 top locked
D4 "1N5406" DO-201AD 43.18,116.84 r180 top
D5 "BAS316,115" sod-323 126.492,28.956 r270 bottom
D6 "C3D04060A" TO-220-F2 12.954,73.152 r90 top locked
D7 "BAS316,115" sod-323 133.35,46.736 r90 bottom
D8 "BAS316,115" sod-323 60.96,116.84 r270 bottom
D9 "NF" sod-323 17.78,26.416 r180 bottom
D10 "MURA160T3G" SMA 13.335,40.005 r90 top
D11 "NF" sod-323 18.034,51.054 r180 bottom
D12 "MMSZ5248B-7-F" SOD-123 27.94,48.895 r90 bottom
F1 "0216008.MXESPP" FUSE_0216 106.045,117.475 r0 top
Fx1 "TESTPOINT" PAD_100mil-40milhole 137.16,5.08 r0 top
Fx2 "TESTPOINT" PAD_100mil-40milhole 22.86,151.13 r0 top
Fx3 "TESTPOINT" PAD_100mil-40milhole 5.08,5.08 r0 top
HS1-Pin1 "5012" Keystone5012#1 5.08,151.13 r90 top
HS1-Pin2 "5012" Keystone5012#1 5.08,91.313 r90 top
HS3-Pin1 "5012" Keystone5012#1 5.08,21.209 r90 top
HS3-Pin2 "5012" Keystone5012#1 5.08,81.153 r90 top
HS4-ML26AAG-1 "5012" Keystone5012#1 130.175,16.891 r270 top
HS4-ML26AAG-2 "5012" Keystone5012#1 130.175,58.674 r270 top
J1 "1715721" PhoenixContact_1715721 131.318,99.06 r90 top
J2 "39357-0002" Molex_39357-0002 132.715,78.105 r90 top
J3 "39357-0002" Molex_39357-0002 132.334,108.458 r90 top
J4 "800-10-002-10-001000" Mill-Max_800-10-002-10-001000 27.305,66.04 r180 top
J5 "39357-0002" Molex_39357-0002 132.715,69.85 r90 top
J6 "1-1318301-3" TE_1-1318301-3 134.62,132.08 r270 top
J7 "923345-03-C" 923345-03-C 17.145,66.04 r0 top
J8 "1732720" Phoenix_1732720 41.91,8.255 r0 top
L1 "744834101" WE-CMBH 97.536,138.43 r270 top
L2 "744834433" WE-CMBH 46.482,138.43 r270 top
L3 "750316597" 750316597 40.894,89.916 r180 top
L4 "750316600" 750316600 43.688,33.528 r180 top
Q1 "2N7002-7-F" SOT-23 124.46,94.75 r270 bottom
Q2 "MMBT4403" SOT-23 120.015,107.95 r180 bottom
Q3 "2N7002-7-F" SOT-23 125.73,77.47 r90 bottom
Q4 "BSS123" SOT-23 130.048,29.21 r90 bottom
Q5 "IPP60R180C7" TO-220AB 12.954,99.314 r90 top locked
Q6 "STB45N65M5" DDPAK 63.5,116.84 r0 top
Q7 "BSS138" SOT-23 57.785,116.84 r90 bottom
Q8 "IPP60R180C7" TO-220AB 12.954,29.21 r90 top locked
Q9 "BSS123" SOT-23 130.048,46.482 r270 bottom
Q10 "IPP12CN10L G" TO-220AB 130.175,33.655 r180 top
Q11 "IPP60R180C7" TO-220AB 12.954,51.054 r90 top locked
Q12 "IPP12CN10L G" TO-220AB 130.175,41.91 r0 top
R1 "RC0603FR-07100RL" 0603 41.275,88.332 r270 bottom
R2 "CRCW0603100KFKEA" 0603 39.37,82.617 r90 bottom
R3 "CRCW060310K0FKEA" 0603 121.285,94.615 r90 bottom
R4 "RC0603FR-07768KL" 0603 122.085,72.39 r0 bottom
R5 "RC0603FR-07237KL" 0603 118.364,72.39 r0 bottom
R6 "CRCW0603100KFKEA" 0603 37.465,88.332 r270 bottom
R7 "CRCW12063M09FKEA" 1206 42.545,113.859 r90 bottom
R8 "CRCW12063M09FKEA" 1206 42.545,108.779 r90 bottom
R9 "CRCW12063M09FKEA" 1206 42.545,103.699 r90 bottom
R10 "CRCW060310K0FKEA" 0603 125.095,107.95 r90 bottom
R11 "CRCW060310K0FKEA" 0603 118.356,81.153 r0 bottom
R12 "CRCW12063M09FKEA" 1206 39.37,113.859 r90 bottom
R13 "CRCW12063M09FKEA" 1206 39.37,108.779 r90 bottom
R14 "CRCW12063M09FKEA" 1206 39.37,103.699 r90 bottom
R15 "CRCW060310K0FKEA" 0603 127.635,108.585 r180 bottom
R16 "CRCW06031K00FKEA" 0603L 125.73,81.28 r90 bottom
R17 "CRCW120610M0FKEA" 1206 57.404,84.582 r180 bottom
R18 "CRCW120610M0FKEA" 1206 52.254,84.582 r180 bottom
R19 "CRCW120610M0FKEA" 1206 47.174,84.582 r180 bottom
R20 "CRCW06031K00JNEA" 0603 125.73,70.612 r0 bottom
R21 "CRCW0603100KFKEA" 0603 125.73,72.39 r0 bottom
R22 "CRCW060375K0FKEA" 0603 37.465,82.617 r270 bottom
R23 "CRCW06033M30JNEA" 0603 35.56,82.617 r90 bottom
R24 "RC0603FR-07470RL" 0603 26.67,96.587 r270 bottom
R25 "RC0603FR-07470RL" 0603 28.092,92.549 r270 bottom
R26 "CRCW06032K21FKEA" 0603 27.305,82.617 r90 bottom
R27 "CRCW06033K32FKEA" 0603 25.4,88.172 r180 bottom
R28 "ERJ-8ENF4753V" 1206 36.83,133.985 r270 bottom
R29 "CRCW06033R30JNEA" 0603 19.05,100.33 r180 bottom
R30 "RC0603FR-0710RL" 0603 123.698,28.194 r180 bottom
R31 "ERJ-8ENF4753V" 1206 36.83,142.875 r270 bottom
R32 "CRCW0603100KFKEA" 0603 132.08,23.114 r180 bottom
R33 "CRCW0603221KFKEA" 0603 132.08,24.892 r180 bottom
R34 "CRCW060310R0JNEA" 0603 27.432,100.33 r270 bottom
R35 "CRCW06031R00FKEA" 0603 19.05,97.79 r180 bottom
R36 "RC0603FR-0710RL" 0603 123.698,33.02 r90 bottom
R37 "CRCW12060000Z0EA" 1206 29.21,104.394 r180 bottom
R38 "CRCW060310K0FKEA" 0603 16.51,99.06 r90 bottom
R39 "CRA2512-FZ-R080ELF" 2512 19.685,112.895 r90 bottom
R40 "CRA2512-FZ-R080ELF" 2512 24.765,112.895 r90 bottom
R41 "CRA2512-FZ-R080ELF" 2512 14.605,112.895 r90 bottom
R42 "CRCW0603100KFKEA" 0603 57.658,119.634 r180 bottom
R43 "RC0603FR-07221KL" 0603 63.05,116.997 r270 bottom
R44 "RC0603FR-0710RL" 0603 136.144,47.498 r0 bottom
R45 "CRCW0603100KFKEA" 0603 127.762,52.578 r0 bottom
R46 "CRCW0603221KFKEA" 0603 127.762,50.8 r0 bottom
R47 "ERJ-8RQF3R3V" 1206 17.78,23.876 r180 bottom
R48 "CRCW08052R20JNEA" 0805_HV 13.335,42.005 r180 bottom
R49 "RC0603FR-0710RL" 0603 136.144,42.672 r270 bottom
R50 "CRCW060310K0FKEA" 0603 16.51,29.591 r270 bottom
R51 "ERJ-6RQF1R0V" 0805_HV 25.146,43.688 r180 bottom
R52 "ERJ-1TYJ100U" 2512 109.22,27.305 r90 bottom
R53 "CRCW060351R1FKEA" 0603 18.288,40.894 r90 bottom
R54 "CRCW06030000Z0EA" 0603 121.92,33.02 r270 bottom
R55 "CRCW060351R1FKEA" 0603 21.844,40.894 r90 bottom
R56 "ERJ-8RQF3R3V" 1206 18.415,48.26 r180 bottom
R57 "CRCW06030000Z0EA" 0603 137.922,42.672 r90 bottom
R58 "CRCW060310K0FKEA" 0603 17.145,53.975 r90 bottom
R59 "ERJ-1TRQF1R0U" 2512 21.59,60.325 r270 bottom
R60 "ERJ-1TRQF1R0U" 2512 17.145,60.325 r270 bottom
R61 "ERJ-1TRQF1R0U" 2512 12.7,60.325 r270 bottom
R62 "ERJ-1TYJ100U" 2512 109.22,49.53 r270 bottom
R63 "CRCW060320K0FKEA" 0603 24.765,12.065 r270 bottom
R64 "RC0603FR-0749R9L" 0603 25.908,9.144 r0 bottom
R65 "CRCW06030000Z0EA" 0603 27.432,29.422 r270 bottom
R66 "RC0603FR-071K21L" 0603 27.432,26.12 r270 bottom
R67 "CRCW060310K0FKEA" 0603 27.305,12.065 r270 bottom
R68 "RC0603FR-07107KL" 0603 34.29,13.97 r0 bottom
R69 "RC0603FR-0719K6L" 0603 29.845,14.605 r90 bottom
R70 "CRCW060310K0FKEA" 0603 33.655,8.89 r90 bottom
RT1 "B57237S220M" S237 81.28,116.84 r180 top
RV1 "B72214S0271K101" VAR_B72214S0271 127,134.62 r270 top
T1 "750316599" Wurth_750316599 88.9,40.64 r0 top
TP1 "5010" Keystone5010 48.895,121.92 r0 top
TP2 "TESTPOINT" PAD_100mil-40milhole 137.16,151.13 r0 top
TP5 "5010" Keystone5010 30.48,4.445 r0 top
TP6 "5011" Keystone5011 23.495,4.445 r0 top
TP7 "5012" Keystone5012#2 16.51,4.445 r0 top
U1 "TPS7A4201DGNR" DGN0008B_N 118.356,76.708 r90 bottom
U2 "PC817X4NSZ0F" DIP762W60P254L460H350Q4B#1 124.46,87.63 r90 top
U3 "UCC29950DR" D0016A_N 32.385,90.237 r180 bottom
U4 "UCC24610DR" D0008A_N 126.492,23.749 r180 bottom
U5 "UCC27532DBVR" DBV0006A_N 24.13,101.092 r180 bottom
U6 "UCC24610DR" D0008A_N 133.35,51.943 r0 bottom
U7 "UCC27714DR" D0014A_N 20.32,34.925 r270 bottom
U8 "PC817X4NSZ0F" DIP762W60P254L460H350Q4B#2 26.035,19.05 r90 top
U9 "TL431AIDBZR" DBZ0003A_N 30.48,8.89 r270 bottom

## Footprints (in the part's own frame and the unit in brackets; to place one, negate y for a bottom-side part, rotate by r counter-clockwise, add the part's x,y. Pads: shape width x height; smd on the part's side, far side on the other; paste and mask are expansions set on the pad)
0603 [mm] "0603 from SM-752 data"
  rect 1x0.95 smd: 1(-0.8,0) 2(0.8,0)
  silkscreen extent -1.52,-0.69 1.52,0.69, body extent -0.87,-0.47 0.87,0.47, height 1
0603L [mm] "0603 from SM-752 data"
  rect 0.8x0.85 smd: 1(-0.7,0) 2(0.7,0)
  silkscreen extent -0.07,-0.33 0.07,0.33, body extent -0.87,-0.47 0.87,0.47, height 1
0805_HV [mil] "0805 with 30mil clearance between pads"
  rect 50x63 smd: 1(-40,0) 2(40,0)
  silkscreen extent -74,-40 74,40, body extent -43,-29 43,29, height 57
1206 [mm] "1206 from SM-752 data"
  rect 1.3x1.85 smd: 1(-1.45,0) 2(1.45,0)
  silkscreen extent -2.4,-1.21 2.4,1.21, body extent -1.7,-0.9 1.7,0.9, height 1.35
1206_180 [mm] "1206_180"
  rect 1.1x1.6 smd: 1(-1.7,0) 2(1.7,0)
  silkscreen extent -0.9,-1 0.9,1, body extent -1.75,-0.95 1.75,0.95, height 1.8
1210_220 [mm] "1210"
  rect 1.3x2.7 smd: 1(-1.45,0) 2(1.45,0)
  silkscreen extent -2.32,-1.57 2.32,1.57, body extent -1.7,-1.35 1.7,1.35, height 2.2
2512 [mm] "Chip Resistor, Body 6.3x3.2mm, IPC Medium Density"
  rect 1.3x3.4 smd: 1(-2.95,0) 2(2.95,0)
  silkscreen extent -1.9,-1.6 1.9,1.6, body extent -3.22,-1.67 3.22,1.67, height 0.71
923345-03-C [mil] "Wire Jumper"
  round 60 hole 38: 1(-150,0) 2(150,0)
  body extent -163,-40 163,37, height 100
750316597 [mm] "Radial Leaded, 2-Leads, Dia 45mm, Pin Spacing 43mm"
  rrect50% 3x3 hole 1.2: 1(-21.5,0)
  round 3 hole 1.2: 2(21.5,0)
  silkscreen extent -23.43,-22.6 22.6,22.6, body extent -22.5,-22.5 22.5,22.5, height 20
750316600 [mm] "TH, 10-Leads, Body 26.67x26.04mm, Pitch 5mm"
  rrect50% 1.85x1.85 hole 1.32: 1(-11.25,10)
  round 1.85 hole 1.32: 2(-11.25,5) 3(-11.25,0) 4(-11.25,-5) 5(-11.25,-10) 6(11.25,-10) 7(11.25,-5) 8(11.25,0) 9(11.25,5) 10(11.25,10)
  silkscreen extent -13.9,-13.02 13.34,13.02, body extent -13.33,-13.02 13.34,13.02, height 13.6
B_800x700x800 [mm] "TH, 2- Leads, Body 8x7mm, Pin Spacing 7.5mm"
  round 1.4 hole 0.9: 1(-3.75,0) 2(3.75,0)
  silkscreen extent -4,-3.5 4,3.5, body extent -4.05,-3.5 4.05,3.5, height 10.97
CAPRR1500W80L1750T950H1750 [mm] "PANASONIC"
  round 1.7 hole 1.069: 1(-7.5,0) 2(7.5,0)
  silkscreen extent -9,-5 9,5, body extent -9,-5 9,5, height 18
CAPRR1500W80L1800T800H1550 [mm] "RUBYCON"
  round 1.55 hole 1.05: 1(-7.5,0) 2(7.5,0)
  silkscreen extent -9,-4 9,4, body extent -9,-4 9,4, height 16.5
CAPRR2250W80L2550T850H1750 [mm] "PANASONIC"
  round 1.55 hole 1.05: 1(-11.25,0) 2(11.25,0)
  silkscreen extent -12.75,-4.25 12.75,4.25, body extent -12.75,-4.25 12.75,4.25, height 17.5
D0008A_N [mm] "SOIC, 8-Leads, Body 4.9x3.9mm, Pitch 1.27mm, IPC Medium Density"
  oval 1.45x0.6 smd: 1(-2.725,1.905) 2(-2.725,0.635) 3(-2.725,-0.635) 4(-2.725,-1.905) 5(2.725,-1.905) 6(2.725,-0.635) 7(2.725,0.635) 8(2.725,1.905)
  silkscreen extent -3.3,-2.5 0.9,2.5, body extent -3,-2.45 3,2.45, height 1.63
D0014A_N [mm] "SOIC, 14-Leads, Body 8.7x3.9mm, Pitch 1.27mm, IPC Medium Density"
  oval 1.45x0.6 smd: 1(-2.725,3.81) 2(-2.725,2.54) 3(-2.725,1.27) 4(-2.725,0) 5(-2.725,-1.27) 6(-2.725,-2.54) 7(-2.725,-3.81) 8(2.725,-3.81) 9(2.725,-2.54) 10(2.725,-1.27) 11(2.725,0) 12(2.725,1.27) 13(2.725,2.54) 14(2.725,3.81)
  silkscreen extent -3.3,-4.4 0.9,4.4, body extent -3.02,-4.32 3.02,4.32, height 1.6
D0016A_N [mm] "SOIC, 16-Leads, Body 9.9x3.9mm, Pitch 1.27mm, IPC Medium Density"
  oval 1.45x0.6 smd: 1(-2.725,4.445) 2(-2.725,3.175) 3(-2.725,1.905) 4(-2.725,0.635) 5(-2.725,-0.635) 6(-2.725,-1.905) 7(-2.725,-3.175) 8(-2.725,-4.445) 9(2.725,-4.445) 10(2.725,-3.175) 11(2.725,-1.905) 12(2.725,-0.635) 13(2.725,0.635) 14(2.725,1.905) 15(2.725,3.175) 16(2.725,4.445)
  silkscreen extent -3.3,-5 0.9,5, body extent -3,-4.95 3,4.95, height 1.6
DBV0006A_N [mm] "SOT23, 6-Leads, Body 2.9x1.6mm, Pitch 0.95mm, Lead Span 2.8mm, IPC Medium Density"
  rrect17% 1x0.6 smd: 1(-1.375,0.95) 2(-1.375,0) 3(-1.375,-0.95) 4(1.375,-0.95) 5(1.375,0) 6(1.375,0.95)
  silkscreen extent -1.68,-1.55 0.5,1.55, body extent -1.42,-1.46 1.42,1.46, height 1.12
DBZ0003A_N [mm] "SOT23, 3-Leads, Body 2.9x1.3mm, Pitch 0.95mm, Lead Span 2.4mm, IPC Medium Density"
  rrect17% 1x0.6 smd: 1(-1.2,0.95) 2(-1.2,-0.95) 3(1.2,0)
  silkscreen extent -1.65,-1.5 0.7,1.5, body extent -1.26,-1.46 1.26,1.46, height 0.98
DDPAK [mil] "D2-PAK, 3-Pads, Body 9.7x10.4mm (max), TO-263AB, using Vishay Silionix recommended pad sizes"
  rrect8% 135x49.49 smd: 1(-246.06,100) 3(-246.06,-100)
  rrect1% 355x420 smd paste-181.1: 4(155.51,0)
  silkscreen extent -295,-220 344,220, body extent -295,-202 324,202, height 180
DGN0008B_N [mm] "TSOP, 8-Leads, Body 3x3mm, Pitch 0.65mm, Thermal Pad 1.92x1.60mm, IPC Medium Density"
  rrect100% 1.35x0.45 smd: 1(-2.225,0.975) 2(-2.225,0.325) 3(-2.225,-0.325) 4(-2.225,-0.975) 5(2.225,-0.975) 6(2.225,-0.325) 7(2.225,0.325) 8(2.225,0.975)
  rrect5% 1.88x1.98 smd: 9(0,0)
  silkscreen extent -2.7,-1.55 0.95,1.55, body extent -2.46,-1.5 2.46,1.5, height 1.1
DIP762W60P254L460H350Q4B#1 [mm] "LITE-ON"
  rrect8% 1.32x1.32 hole 0.8: 1(-3.81,1.27)
  round 1.32 hole 0.8: 2(-3.81,-1.27) 3(3.81,-1.27) 4(3.81,1.27)
  silkscreen extent -4.29,-2.29 3.25,2.3, body extent -3.94,-2.29 3.94,2.3, height 4.3
DIP762W60P254L460H350Q4B#2 [mm] "LITE-ON"
  rrect8% 1.32x1.32 hole 0.8: 1(-3.81,1.27)
  round 1.32 hole 0.8: 2(-3.81,-1.27) 3(3.81,-1.27)
  round 1.321 hole 0.8: 4(3.81,1.27)
  silkscreen extent -4.29,-2.29 3.25,2.3, body extent -3.94,-2.29 3.94,2.3, height 4.3
DO-201AD [mm] "Vishay dimensions"
  rect 2.1x2.1 hole 1.6: 1(-10.16,0)
  round 2.1 hole 1.6: 2(10.16,0)
  silkscreen extent -7.47,-2.7 7.57,2.61, body extent -10.82,-2.74 10.82,2.61, height 5.33
E_900x700x900 [mm] "TH, 2- Leads, Body 9x7mm, Pin Spacing 7.5mm"
  round 1.4 hole 0.9: 1(-3.75,0) 2(3.75,0)
  silkscreen extent -4.5,-3.5 4.5,3.5, body extent -4.49,-3.5 4.49,3.5, height 11.96
FUSE_0216 [mm] "LITTELFUSE"
  round 1.8 hole 1.041: 1(-13,0) 2(13,0)
  silkscreen extent -11.8,-2.65 11.8,2.65, body extent -13.32,-2.65 13.32,2.65, height 5.3
GBJ [mm] "Micro Commercial Components"
  rect 2.3x2.3 hole 1.6: 1(-12.5,0)
  round 2.3 hole 1.6: 2(-2.5,0) 3(5,0) 4(12.5,0)
  silkscreen extent -15.3,-1.8 15,3.1, body extent -15.25,-1.75 15.05,3.05, height 24.3
Keystone5010 [mil] "Keystone Multipurpose loops"
  round 87 hole 63: 1(0,0)
  silkscreen extent -70,-70 70,70, body extent -63,-63 63,62, height 319
Keystone5011 [mil] "Keystone Multipurpose loops"
  round 87 hole 63: 1(0,0)
  silkscreen extent -70,-70 70,70, body extent -63,-63 63,62, height 319
Keystone5012#1 [mm] "Keystone Multipurpose loops"
  round 6 hole 3.2: 1(0,0)
  silkscreen extent -1.78,-1.78 1.78,1.78, body extent -1.6,-1.6 1.59,1.59, height 8.1
Keystone5012#2 [mm] "Keystone Multipurpose loops"
  round 2.21 hole 1.6: 1(0,0)
  silkscreen extent -1.78,-1.78 1.78,1.78, body extent -1.6,-1.6 1.59,1.59, height 8.1
KXW_1800x4500 [mm] "TH, 2-Leads, Dia 18mm, Pin Spacing 7.5mm"
  rect 1.55x1.55 hole 1.05: 1(-3.75,0)
  round 1.55 hole 1.05: 2(3.75,0)
  silkscreen extent -9.25,-9.25 9.25,9.25, body extent -9.25,-9.25 9.26,9.25, height 47.01
Mill-Max_800-10-002-10-001000 [mm] "Mill-Max"
  rect 1.5x1.5 hole 0.85: 1(-1.27,0)
  round 1.5 hole 0.85: 2(1.27,0)
  silkscreen extent -2.54,-1.27 2.54,1.78, body extent -2.54,-1.27 2.54,1.27, height 8.13
Molex_39357-0002 [mm] "Terminal Block, 3.5 mm, 2x1, TH"
  rect 1.6x1.6 hole 1.1: 1(-1.75,0)
  round 1.6 hole 1.1: 2(1.75,0)
  silkscreen extent -3.86,-3.45 3.5,3.84, body extent -3.55,-3.45 3.56,3.84, height 8.51
PAD_100mil-40milhole [mm]
  round 6 hole 3.2: 1(0,0)
Phoenix_1732720 [mm] "Phoenix Contact"
  rect 2x2 hole 1.3 paste+0 mask+0.05: 1(-3.81,-1.1)
  round 2 hole 1.3 paste+0 mask+0.05: 2(3.81,-1.1)
  silkscreen extent -8.91,-6.4 7.62,6.4, body extent -8.19,-6.4 7.62,6.4, height 18.3
PhoenixContact_1715721 [mm] "Phoenix Contact 1715721 used on LM3445 design from Longmont"
  rrect5% 1.905x1.905 hole 1.3: 1(-2.54,0)
  round 1.9 hole 1.3: 2(2.54,0)
  silkscreen extent -5.82,-5.25 5.08,5.2, body extent -5.82,-4.6 5.08,5.2, height 14.2
S237 [mm] "EPCOS"
  round 1.75 hole 1.1: 1(-3.75,0) 2(3.75,0)
  silkscreen extent -7.5,-3.5 7.5,3.5, body extent -7.47,-3.5 7.47,3.5, height 21.99
SMA [mm] "Molded Diode, 2-Leads, Body 4.3x2.6mm, IPC Medium Density, based on OnSemi component dimensions and land pattern"
  rect 2x2 smd: 1(-2,0) 2(2,0)
  silkscreen extent -3.66,-1.57 2.79,1.57, body extent -2.6,-1.3 2.6,1.3, height 2.42
SOD-123 [mm] "On Semi recommended land pattern"
  rect 0.915x1.22 smd: 1(-1.637,0) 2(1.637,0)
  silkscreen extent -2.74,-1.17 2.03,1.17, body extent -1.93,-0.9 1.93,0.9, height 1.35
sod-323 [mm] "NXP recommended land pattern"
  rect 0.6x0.6 smd paste-0.05: 1(-1.1,0) 2(1.1,0)
  silkscreen extent -2.06,-0.86 1.53,0.86, body extent -1.3,-0.67 1.3,0.68, height 1.1
SOT-23 [mm] "SOT23, 3-Leads, Body 2.9x1.3mm, Pitch 0.95mm, Lead Span 2.5mm, IPC Medium Density"
  rrect50% 1x0.6 smd: 1(-1.2,0.95) 2(-1.2,-0.95) 3(1.2,0)
  silkscreen extent -1.63,-1.5 0.7,1.5, body extent -1.16,-1.45 1.21,1.45, height 1
TE_1-1318301-3 [mm] "TE"
  rect 2.9x2.9 hole 2.15: 1(-7.925,0)
  round 2.9 hole 2.15: 2(0,0) 3(7.925,0)
  silkscreen extent -10.13,-4.53 10.08,4.46, body extent -9.87,-4.28 9.87,4.22, height 10.72
TO-220-F2 [mm] "CREE"
  rect 1.9x1.9 hole 1.4: 1(-2.54,0)
  round 1.9 hole 1.4: 2(2.54,0)
  silkscreen extent -5.25,-1.64 5.26,3.01, body extent -5.25,-1.64 5.26,3.01, height 19.09
TO-220AB [mm] "Copied from Altium's version of TO3B"
  rrect25% 1.93x3 hole 1.27: 1(-2.54,0)
  oval 1.93x3 hole 1.27: 2(0,0) 3(2.54,0)
  silkscreen extent -5.61,-1.49 5.61,3.2, body extent -5.61,-1.49 5.61,3.2, height 19.42
VAR_B72214S0271 [mm] "EPCOS"
  round 1.7 hole 1.067: 1(-3.75,1.1) 2(3.75,-1.1)
  silkscreen extent -7.7,-2.5 7.7,2.5, body extent -7.74,-2.5 7.7,2.5, height 18.48
WE-CMBH [mm] "THT Inductor, 4-Leads, Body 28 x 32.5mm"
  rect 2x2 hole 1.2: 1(-6.25,13.75)
  round 2 hole 1.2: 2(-6.25,-13.75) 3(6.25,-13.75) 4(6.25,13.75)
  silkscreen extent -14,-16.25 14,17, body extent -13.83,-16.25 13.83,16.25, height 20
Wurth_750316599 [mm] "TH, 18-Leads, Body 62x49mm, Pitch 5.45mm"
  rect 1.85x1.85 hole 1.32: 1(-26.7,21.8)
  round 1.85 hole 1.32: 2(-26.7,16.35) 3(-26.7,10.9) 4(-26.7,5.45) 5(-26.7,0) 6(-26.7,-5.45) 7(-26.7,-10.9) 8(-26.7,-16.35) 9(-26.7,-21.8) 10(26.7,-21.8) 11(26.7,-16.35) 12(26.7,-10.9) 13(26.7,-5.45) 14(26.7,0) 15(26.7,5.45) 16(26.7,10.9) 17(26.7,16.35) 18(26.7,21.8)
  silkscreen extent -31.5,-24.5 31,24.5, body extent -31,-24.5 31,24.5, height 20
ZLH_1250x2500 [mm] "Rubycon"
  rect 1.5x1.5 hole 0.85: 1(-2.5,0)
  round 1.5 hole 0.85: 2(2.5,0)
  silkscreen extent -6.6,-6.6 6.6,6.6, body extent -6.45,-6.49 6.49,6.49, height 26.51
